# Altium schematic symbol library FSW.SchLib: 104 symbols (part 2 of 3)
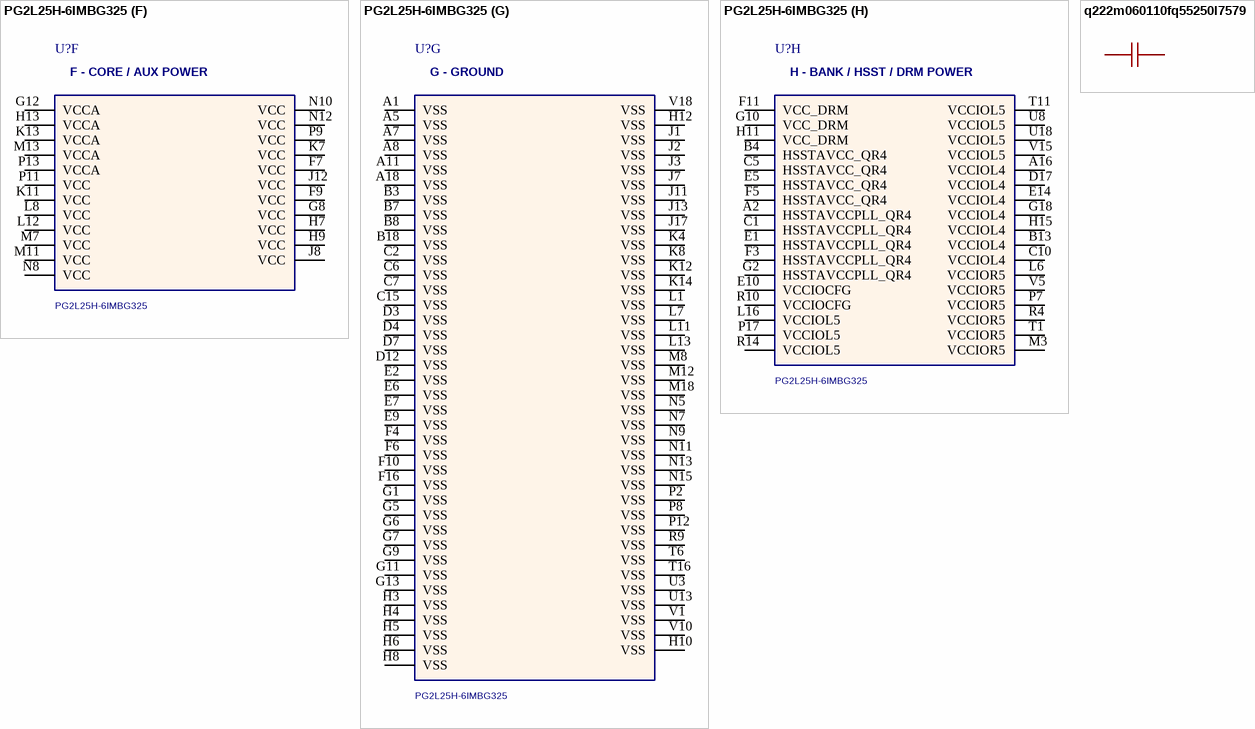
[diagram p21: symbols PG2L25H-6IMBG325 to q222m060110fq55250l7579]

## PG2L25H-6IMBG325
designator U?  (value not drawn)
PANGO Logos2 FPGA; 8 parts; 324 balls; PK04004 V1.1 verified; Reference: OPHW-V1.0.pdf pp2-4
footprint PANGO_MBG325_15X15_P080 (PK04004 V1.1: 324 balls, 15x15mm, 0.8mm pitch; top-view A1 upper-left; nominal 3D 1.30mm, max height 1.45mm)
part A pins: E8 CFG_CLK (io) "OPHW-V1.0.pdf pages 2-4; ball E8", E11 VCCB (power) "OPHW-V1.0.pdf pages 2-4; ball E11", E12 SCBV (in) "OPHW-V1.0.pdf pages 2-4; ball E12", F8 TCK (in) "OPHW-V1.0.pdf pages 2-4; ball F8", F12 CFG_DONE (io) "Bidirectional open-drain. External pull-up required. UG040005 V1.3.", F13 MODE_2 (in) "OPHW-V1.0.pdf pages 2-4; ball F13", J9 VSSADC (power) "OPHW-V1.0.pdf pages 2-4; ball J9", J10 VCCADC (power) "OPHW-V1.0.pdf pages 2-4; ball J10", K9 VREFADC_N (in) "OPHW-V1.0.pdf pages 2-4; ball K9", K10 VAADC_P (in) "OPHW-V1.0.pdf pages 2-4; ball K10", L9 VAADC_N (in) "OPHW-V1.0.pdf pages 2-4; ball L9", L10 VREFADC_P (in) "OPHW-V1.0.pdf pages 2-4; ball L10", M9 TSDN "OPHW-V1.0.pdf pages 2-4; ball M9", M10 TSDP "OPHW-V1.0.pdf pages 2-4; ball M10", P10 RSTN (in) "OPHW-V1.0.pdf pages 2-4; ball P10", R8 TMS (in) "OPHW-V1.0.pdf pages 2-4; ball R8", R11 MODE_1 (in) "OPHW-V1.0.pdf pages 2-4; ball R11", R12 MODE_0 (in) "OPHW-V1.0.pdf pages 2-4; ball R12", T8 TDO (out) "OPHW-V1.0.pdf pages 2-4; ball T8", T9 TDI (in) "OPHW-V1.0.pdf pages 2-4; ball T9", T10 INIT_FLAG_N (io) "Bidirectional open-drain. External pull-up required. UG040005 V1.3."
part B pins: J14 DIFFIO_L5_G0_04P_D6 (io) "OPHW-V1.0.pdf pages 2-4; ball J14", J15 DIFFIO_L5_G0_01P_D2 (io) "OPHW-V1.0.pdf pages 2-4; ball J15", J16 DIFFIO_L5_G0_01N_D3 (io) "OPHW-V1.0.pdf pages 2-4; ball J16", J18 DIFFIO_L5_G0_02P_DQS_IO_STATUS_C (io) "OPHW-V1.0.pdf pages 2-4; ball J18", K15 DIFFIO_L5_G0_04N_D7 (io) "OPHW-V1.0.pdf pages 2-4; ball K15", K16 DIFFIO_L5_G0_00P_MOSI_D0 (io) "OPHW-V1.0.pdf pages 2-4; ball K16", K17 DIFFIO_L5_G0_03P_D4 (io) "OPHW-V1.0.pdf pages 2-4; ball K17", K18 DIFFIO_L5_G0_02N_DQS_ECCLKIN (io) "OPHW-V1.0.pdf pages 2-4; ball K18", L14 SIO_L5_00 (io) "OPHW-V1.0.pdf pages 2-4; ball L14", L15 DIFFIO_L5_G0_05P_FCS_N (io) "OPHW-V1.0.pdf pages 2-4; ball L15", L17 DIFFIO_L5_G0_00N_MISO_D1_DI (io) "OPHW-V1.0.pdf pages 2-4; ball L17", L18 DIFFIO_L5_G0_03N_D5 (io) "OPHW-V1.0.pdf pages 2-4; ball L18", M14 DIFFIO_L5_G1_07P_D11 (io) "OPHW-V1.0.pdf pages 2-4; ball M14", M15 DIFFIO_L5_G0_05N_VREF_D8 (io) "OPHW-V1.0.pdf pages 2-4; ball M15", M16 DIFFIO_L5_G1_06P_D9 (io) "OPHW-V1.0.pdf pages 2-4; ball M16", M17 DIFFIO_L5_G1_06N_D10 (io) "OPHW-V1.0.pdf pages 2-4; ball M17", N14 DIFFIO_L5_G1_07N_D12 (io) "OPHW-V1.0.pdf pages 2-4; ball N14", N16 DIFFIO_L5_G1_08P_DQS (io) "OPHW-V1.0.pdf pages 2-4; ball N16", N17 DIFFIO_L5_G1_08N_DQS_D13 (io) "OPHW-V1.0.pdf pages 2-4; ball N17", N18 DIFFIO_L5_G1_09P_D14 (io) "OPHW-V1.0.pdf pages 2-4; ball N18", P14 DIFFIO_L5_G1_11P_GMCLK (io) "OPHW-V1.0.pdf pages 2-4; ball P14", P15 DIFFIO_L5_G1_10P_GSCLK (io) "OPHW-V1.0.pdf pages 2-4; ball P15", P16 DIFFIO_L5_G1_10N_GSCLK (io) "OPHW-V1.0.pdf pages 2-4; ball P16", P18 DIFFIO_L5_G1_09N_D15 (io) "OPHW-V1.0.pdf pages 2-4; ball P18", R13 DIFFIO_L5_G3_18P_D26_A10 (io) "OPHW-V1.0.pdf pages 2-4; ball R13", R15 DIFFIO_L5_G1_11N_GMCLK (io) "OPHW-V1.0.pdf pages 2-4; ball R15", R16 DIFFIO_L5_G2_13P_GSCLK (io) "OPHW-V1.0.pdf pages 2-4; ball R16", R17 DIFFIO_L5_G2_13N_GSCLK (io) "OPHW-V1.0.pdf pages 2-4; ball R17", R18 DIFFIO_L5_G2_14P_DQS_RWSEL (io) "OPHW-V1.0.pdf pages 2-4; ball R18", T12 DIFFIO_L5_G3_21P_D21_A5 (io) "OPHW-V1.0.pdf pages 2-4; ball T12", T13 DIFFIO_L5_G3_18N_VREF_D25_A9 (io) "OPHW-V1.0.pdf pages 2-4; ball T13", T14 DIFFIO_L5_G2_12P_GMCLK (io) "OPHW-V1.0.pdf pages 2-4; ball T14", T15 DIFFIO_L5_G2_12N_GMCLK (io) "OPHW-V1.0.pdf pages 2-4; ball T15", T17 DIFFIO_L5_G2_15P_CS_N (io) "OPHW-V1.0.pdf pages 2-4; ball T17", T18 DIFFIO_L5_G2_14N_DQS_CSO_DOUT (io) "OPHW-V1.0.pdf pages 2-4; ball T18", U9 DIFFIO_L5_G3_23P_D17_A1 (io) "OPHW-V1.0.pdf pages 2-4; ball U9", U10 SIO_L5_01 (io) "OPHW-V1.0.pdf pages 2-4; ball U10", U11 DIFFIO_L5_G3_22P_D19_A3 (io) "OPHW-V1.0.pdf pages 2-4; ball U11", U12 DIFFIO_L5_G3_21N_D20_A4 (io) "OPHW-V1.0.pdf pages 2-4; ball U12", U14 DIFFIO_L5_G3_19P_D24_A8 (io) "OPHW-V1.0.pdf pages 2-4; ball U14", U15 DIFFIO_L5_G2_16P_D30_A14 (io) "OPHW-V1.0.pdf pages 2-4; ball U15", U16 DIFFIO_L5_G2_16N_D29_A13 (io) "OPHW-V1.0.pdf pages 2-4; ball U16", U17 DIFFIO_L5_G2_15N_D31_A15 (io) "OPHW-V1.0.pdf pages 2-4; ball U17", V9 DIFFIO_L5_G3_23N_D16_A0 (io) "OPHW-V1.0.pdf pages 2-4; ball V9", V11 DIFFIO_L5_G3_22N_D18_A2 (io) "OPHW-V1.0.pdf pages 2-4; ball V11", V12 DIFFIO_L5_G3_20P_DQS (io) "OPHW-V1.0.pdf pages 2-4; ball V12", V13 DIFFIO_L5_G3_20N_DQS_D22_A6 (io) "OPHW-V1.0.pdf pages 2-4; ball V13", V14 DIFFIO_L5_G3_19N_D23_A7 (io) "OPHW-V1.0.pdf pages 2-4; ball V14", V16 DIFFIO_L5_G2_17P_D28_A12 (io) "OPHW-V1.0.pdf pages 2-4; ball V16", V17 DIFFIO_L5_G2_17N_D27_A11 (io) "OPHW-V1.0.pdf pages 2-4; ball V17"
part C pins: A9 DIFFIO_L4_G0_02N_DQS_VAA3N (io) "OPHW-V1.0.pdf pages 2-4; ball A9", A10 DIFFIO_L4_G0_04N_VAA5N (io) "OPHW-V1.0.pdf pages 2-4; ball A10", A12 DIFFIO_L4_G1_06N_VAA7N (io) "OPHW-V1.0.pdf pages 2-4; ball A12", A13 DIFFIO_L4_G1_07P_VAA8P (io) "OPHW-V1.0.pdf pages 2-4; ball A13", A14 DIFFIO_L4_G1_07N_VAA8N (io) "OPHW-V1.0.pdf pages 2-4; ball A14", A15 DIFFIO_L4_G1_09N_VAA10N (io) "OPHW-V1.0.pdf pages 2-4; ball A15", A17 DIFFIO_L4_G2_14N_DQS_BADRVO_N (io) "OPHW-V1.0.pdf pages 2-4; ball A17", B9 DIFFIO_L4_G0_02P_DQS_VAA3P (io) "OPHW-V1.0.pdf pages 2-4; ball B9", B10 DIFFIO_L4_G0_04P_VAA5P (io) "OPHW-V1.0.pdf pages 2-4; ball B10", B11 DIFFIO_L4_G0_03N (io) "OPHW-V1.0.pdf pages 2-4; ball B11", B12 DIFFIO_L4_G1_06P_VAA7P (io) "OPHW-V1.0.pdf pages 2-4; ball B12", B14 DIFFIO_L4_G1_09P_VAA10P (io) "OPHW-V1.0.pdf pages 2-4; ball B14", B15 DIFFIO_L4_G1_08N_DQS_VAA9N (io) "OPHW-V1.0.pdf pages 2-4; ball B15", B16 DIFFIO_L4_G2_14P_DQS (io) "OPHW-V1.0.pdf pages 2-4; ball B16", B17 DIFFIO_L4_G2_15N_A27 (io) "OPHW-V1.0.pdf pages 2-4; ball B17", C8 DIFFIO_L4_G0_00N_VAA1N (io) "OPHW-V1.0.pdf pages 2-4; ball C8", C9 DIFFIO_L4_G0_01N_VAA2N (io) "OPHW-V1.0.pdf pages 2-4; ball C9", C11 DIFFIO_L4_G0_03P (io) "OPHW-V1.0.pdf pages 2-4; ball C11", C12 DIFFIO_L4_G0_05N_VREF (io) "OPHW-V1.0.pdf pages 2-4; ball C12", C13 DIFFIO_L4_G1_10N_GSCLK (io) "OPHW-V1.0.pdf pages 2-4; ball C13", C14 DIFFIO_L4_G1_08P_DQS_VAA9P (io) "OPHW-V1.0.pdf pages 2-4; ball C14", C16 DIFFIO_L4_G2_15P_A28 (io) "OPHW-V1.0.pdf pages 2-4; ball C16", C17 DIFFIO_L4_G2_17P_A24 (io) "OPHW-V1.0.pdf pages 2-4; ball C17", C18 DIFFIO_L4_G2_17N_A23 (io) "OPHW-V1.0.pdf pages 2-4; ball C18", D8 DIFFIO_L4_G0_00P_VAA1P (io) "OPHW-V1.0.pdf pages 2-4; ball D8", D9 DIFFIO_L4_G0_01P_VAA2P (io) "OPHW-V1.0.pdf pages 2-4; ball D9", D10 SIO_L4_00 (io) "OPHW-V1.0.pdf pages 2-4; ball D10", D11 DIFFIO_L4_G0_05P (io) "OPHW-V1.0.pdf pages 2-4; ball D11", D13 DIFFIO_L4_G1_10P_GSCLK (io) "OPHW-V1.0.pdf pages 2-4; ball D13", D14 DIFFIO_L4_G1_11N_GMCLK (io) "OPHW-V1.0.pdf pages 2-4; ball D14", D15 DIFFIO_L4_G2_12N_GMCLK (io) "OPHW-V1.0.pdf pages 2-4; ball D15", D16 DIFFIO_L4_G2_13N_GSCLK (io) "OPHW-V1.0.pdf pages 2-4; ball D16", D18 DIFFIO_L4_G2_16N_A25 (io) "OPHW-V1.0.pdf pages 2-4; ball D18", E13 DIFFIO_L4_G1_11P_GMCLK (io) "OPHW-V1.0.pdf pages 2-4; ball E13", E15 DIFFIO_L4_G2_12P_GMCLK (io) "OPHW-V1.0.pdf pages 2-4; ball E15", E16 DIFFIO_L4_G2_13P_GSCLK (io) "OPHW-V1.0.pdf pages 2-4; ball E16", E17 DIFFIO_L4_G2_16P_A26 (io) "OPHW-V1.0.pdf pages 2-4; ball E17", E18 DIFFIO_L4_G3_23N_VS0 (io) "OPHW-V1.0.pdf pages 2-4; ball E18", F14 DIFFIO_L4_G3_21N_A16 (io) "OPHW-V1.0.pdf pages 2-4; ball F14", F15 DIFFIO_L4_G3_20N_DQS_A18 (io) "OPHW-V1.0.pdf pages 2-4; ball F15", F17 DIFFIO_L4_G3_23P_VS1 (io) "OPHW-V1.0.pdf pages 2-4; ball F17", F18 DIFFIO_L4_G3_18N_VREF_A21 (io) "OPHW-V1.0.pdf pages 2-4; ball F18", G14 DIFFIO_L4_G3_21P_A17 (io) "OPHW-V1.0.pdf pages 2-4; ball G14", G15 DIFFIO_L4_G3_20P_DQS (io) "OPHW-V1.0.pdf pages 2-4; ball G15", G16 DIFFIO_L4_G3_19N_A19 (io) "OPHW-V1.0.pdf pages 2-4; ball G16", G17 DIFFIO_L4_G3_18P_A22 (io) "OPHW-V1.0.pdf pages 2-4; ball G17", H14 SIO_L4_01 (io) "OPHW-V1.0.pdf pages 2-4; ball H14", H16 DIFFIO_L4_G3_19P_A20 (io) "OPHW-V1.0.pdf pages 2-4; ball H16", H17 DIFFIO_L4_G3_22P_BFOE_N (io) "OPHW-V1.0.pdf pages 2-4; ball H17", H18 DIFFIO_L4_G3_22N_BFWE_FCS2_N (io) "OPHW-V1.0.pdf pages 2-4; ball H18"
part D pins: J4 DIFFIO_R5_G0_01N (io) "OPHW-V1.0.pdf pages 2-4; ball J4", J5 DIFFIO_R5_G0_01P (io) "OPHW-V1.0.pdf pages 2-4; ball J5", J6 SIO_R5_00 (io) "OPHW-V1.0.pdf pages 2-4; ball J6", K1 DIFFIO_R5_G0_02N_DQS (io) "OPHW-V1.0.pdf pages 2-4; ball K1", K2 DIFFIO_R5_G0_02P_DQS (io) "OPHW-V1.0.pdf pages 2-4; ball K2", K3 DIFFIO_R5_G0_03P (io) "OPHW-V1.0.pdf pages 2-4; ball K3", K5 DIFFIO_R5_G0_00N (io) "OPHW-V1.0.pdf pages 2-4; ball K5", K6 DIFFIO_R5_G0_00P (io) "OPHW-V1.0.pdf pages 2-4; ball K6", L2 DIFFIO_R5_G0_03N (io) "OPHW-V1.0.pdf pages 2-4; ball L2", L3 DIFFIO_R5_G0_04N (io) "OPHW-V1.0.pdf pages 2-4; ball L3", L4 DIFFIO_R5_G0_04P (io) "OPHW-V1.0.pdf pages 2-4; ball L4", L5 DIFFIO_R5_G0_05P (io) "OPHW-V1.0.pdf pages 2-4; ball L5", M1 DIFFIO_R5_G1_06N (io) "OPHW-V1.0.pdf pages 2-4; ball M1", M2 DIFFIO_R5_G1_06P (io) "OPHW-V1.0.pdf pages 2-4; ball M2", M4 DIFFIO_R5_G1_09P (io) "OPHW-V1.0.pdf pages 2-4; ball M4", M5 DIFFIO_R5_G0_05N_VREF (io) "OPHW-V1.0.pdf pages 2-4; ball M5", M6 DIFFIO_R5_G1_07P (io) "OPHW-V1.0.pdf pages 2-4; ball M6", N1 DIFFIO_R5_G1_08P_DQS (io) "OPHW-V1.0.pdf pages 2-4; ball N1", N2 DIFFIO_R5_G1_10N_GSCLK (io) "OPHW-V1.0.pdf pages 2-4; ball N2", N3 DIFFIO_R5_G1_10P_GSCLK (io) "OPHW-V1.0.pdf pages 2-4; ball N3", N4 DIFFIO_R5_G1_09N (io) "OPHW-V1.0.pdf pages 2-4; ball N4", N6 DIFFIO_R5_G1_07N (io) "OPHW-V1.0.pdf pages 2-4; ball N6", P1 DIFFIO_R5_G1_08N_DQS (io) "OPHW-V1.0.pdf pages 2-4; ball P1", P3 DIFFIO_R5_G1_11N_GMCLK (io) "OPHW-V1.0.pdf pages 2-4; ball P3", P4 DIFFIO_R5_G1_11P_GMCLK (io) "OPHW-V1.0.pdf pages 2-4; ball P4", P5 DIFFIO_R5_G3_18N_VREF (io) "OPHW-V1.0.pdf pages 2-4; ball P5", P6 DIFFIO_R5_G3_18P (io) "OPHW-V1.0.pdf pages 2-4; ball P6", R1 DIFFIO_R5_G2_12N_GMCLK (io) "OPHW-V1.0.pdf pages 2-4; ball R1", R2 DIFFIO_R5_G2_12P_GMCLK (io) "OPHW-V1.0.pdf pages 2-4; ball R2", R3 DIFFIO_R5_G2_13P_GSCLK (io) "OPHW-V1.0.pdf pages 2-4; ball R3", R5 DIFFIO_R5_G3_20P_DQS (io) "OPHW-V1.0.pdf pages 2-4; ball R5", R6 SIO_R5_01 (io) "OPHW-V1.0.pdf pages 2-4; ball R6", R7 DIFFIO_R5_G3_21P (io) "OPHW-V1.0.pdf pages 2-4; ball R7", T2 DIFFIO_R5_G2_13N_GSCLK (io) "OPHW-V1.0.pdf pages 2-4; ball T2", T3 DIFFIO_R5_G2_16N (io) "OPHW-V1.0.pdf pages 2-4; ball T3", T4 DIFFIO_R5_G2_16P (io) "OPHW-V1.0.pdf pages 2-4; ball T4", T5 DIFFIO_R5_G3_20N_DQS (io) "OPHW-V1.0.pdf pages 2-4; ball T5", T7 DIFFIO_R5_G3_21N (io) "OPHW-V1.0.pdf pages 2-4; ball T7", U1 DIFFIO_R5_G2_14N_DQS (io) "OPHW-V1.0.pdf pages 2-4; ball U1", U2 DIFFIO_R5_G2_14P_DQS (io) "OPHW-V1.0.pdf pages 2-4; ball U2", U4 DIFFIO_R5_G2_17P (io) "OPHW-V1.0.pdf pages 2-4; ball U4", U5 DIFFIO_R5_G3_19N (io) "OPHW-V1.0.pdf pages 2-4; ball U5", U6 DIFFIO_R5_G3_19P (io) "OPHW-V1.0.pdf pages 2-4; ball U6", U7 DIFFIO_R5_G3_22P (io) "OPHW-V1.0.pdf pages 2-4; ball U7", V2 DIFFIO_R5_G2_15N (io) "OPHW-V1.0.pdf pages 2-4; ball V2", V3 DIFFIO_R5_G2_15P (io) "OPHW-V1.0.pdf pages 2-4; ball V3", V4 DIFFIO_R5_G2_17N (io) "OPHW-V1.0.pdf pages 2-4; ball V4", V6 DIFFIO_R5_G3_22N (io) "OPHW-V1.0.pdf pages 2-4; ball V6", V7 DIFFIO_R5_G3_23N (io) "OPHW-V1.0.pdf pages 2-4; ball V7", V8 DIFFIO_R5_G3_23P (io) "OPHW-V1.0.pdf pages 2-4; ball V8"
part E pins: A3 HSSTRX2N_QR4 (in) "OPHW-V1.0.pdf pages 2-4; ball A3", A4 HSSTRX2P_QR4 (in) "OPHW-V1.0.pdf pages 2-4; ball A4", A6 HSSTRREF_QR4 (in) "OPHW-V1.0.pdf pages 2-4; ball A6", B1 HSSTTX0N_QR4 (out) "OPHW-V1.0.pdf pages 2-4; ball B1", B2 HSSTTX0P_QR4 (out) "OPHW-V1.0.pdf pages 2-4; ball B2", B5 HSSTREFCLK0N_QR4 (in) "OPHW-V1.0.pdf pages 2-4; ball B5", B6 HSSTREFCLK0P_QR4 (in) "OPHW-V1.0.pdf pages 2-4; ball B6", C3 HSSTRX1N_QR4 (in) "OPHW-V1.0.pdf pages 2-4; ball C3", C4 HSSTRX1P_QR4 (in) "OPHW-V1.0.pdf pages 2-4; ball C4", D1 HSSTTX1N_QR4 (out) "OPHW-V1.0.pdf pages 2-4; ball D1", D2 HSSTTX1P_QR4 (out) "OPHW-V1.0.pdf pages 2-4; ball D2", D5 HSSTREFCLK1N_QR4 (in) "OPHW-V1.0.pdf pages 2-4; ball D5", D6 HSSTREFCLK1P_QR4 (in) "OPHW-V1.0.pdf pages 2-4; ball D6", E3 HSSTRX3N_QR4 (in) "OPHW-V1.0.pdf pages 2-4; ball E3", E4 HSSTRX3P_QR4 (in) "OPHW-V1.0.pdf pages 2-4; ball E4", F1 HSSTTX2N_QR4 (out) "OPHW-V1.0.pdf pages 2-4; ball F1", F2 HSSTTX2P_QR4 (out) "OPHW-V1.0.pdf pages 2-4; ball F2", G3 HSSTRX0N_QR4 (in) "OPHW-V1.0.pdf pages 2-4; ball G3", G4 HSSTRX0P_QR4 (in) "OPHW-V1.0.pdf pages 2-4; ball G4", H1 HSSTTX3N_QR4 (out) "OPHW-V1.0.pdf pages 2-4; ball H1", H2 HSSTTX3P_QR4 (out) "OPHW-V1.0.pdf pages 2-4; ball H2"
part F pins: F7 VCC (power) "OPHW-V1.0.pdf pages 2-4; ball F7", F9 VCC (power) "OPHW-V1.0.pdf pages 2-4; ball F9", G8 VCC (power) "OPHW-V1.0.pdf pages 2-4; ball G8", G12 VCCA (power) "OPHW-V1.0.pdf pages 2-4; ball G12", H7 VCC (power) "OPHW-V1.0.pdf pages 2-4; ball H7", H9 VCC (power) "OPHW-V1.0.pdf pages 2-4; ball H9", H13 VCCA (power) "OPHW-V1.0.pdf pages 2-4; ball H13", J8 VCC (power) "OPHW-V1.0.pdf pages 2-4; ball J8", J12 VCC (power) "OPHW-V1.0.pdf pages 2-4; ball J12", K7 VCC (power) "OPHW-V1.0.pdf pages 2-4; ball K7", K11 VCC (power) "OPHW-V1.0.pdf pages 2-4; ball K11", K13 VCCA (power) "OPHW-V1.0.pdf pages 2-4; ball K13", L8 VCC (power) "OPHW-V1.0.pdf pages 2-4; ball L8", L12 VCC (power) "OPHW-V1.0.pdf pages 2-4; ball L12", M7 VCC (power) "OPHW-V1.0.pdf pages 2-4; ball M7", M11 VCC (power) "OPHW-V1.0.pdf pages 2-4; ball M11", M13 VCCA (power) "OPHW-V1.0.pdf pages 2-4; ball M13", N8 VCC (power) "OPHW-V1.0.pdf pages 2-4; ball N8", N10 VCC (power) "OPHW-V1.0.pdf pages 2-4; ball N10", N12 VCC (power) "OPHW-V1.0.pdf pages 2-4; ball N12", P9 VCC (power) "OPHW-V1.0.pdf pages 2-4; ball P9", P11 VCC (power) "OPHW-V1.0.pdf pages 2-4; ball P11", P13 VCCA (power) "OPHW-V1.0.pdf pages 2-4; ball P13"
part G pins: A1 VSS (power) "OPHW-V1.0.pdf pages 2-4; ball A1", A5 VSS (power) "OPHW-V1.0.pdf pages 2-4; ball A5", A7 VSS (power) "OPHW-V1.0.pdf pages 2-4; ball A7", A8 VSS (power) "OPHW-V1.0.pdf pages 2-4; ball A8", A11 VSS (power) "OPHW-V1.0.pdf pages 2-4; ball A11", A18 VSS (power) "OPHW-V1.0.pdf pages 2-4; ball A18", B3 VSS (power) "OPHW-V1.0.pdf pages 2-4; ball B3", B7 VSS (power) "OPHW-V1.0.pdf pages 2-4; ball B7", B8 VSS (power) "OPHW-V1.0.pdf pages 2-4; ball B8", B18 VSS (power) "OPHW-V1.0.pdf pages 2-4; ball B18", C2 VSS (power) "OPHW-V1.0.pdf pages 2-4; ball C2", C6 VSS (power) "OPHW-V1.0.pdf pages 2-4; ball C6", C7 VSS (power) "OPHW-V1.0.pdf pages 2-4; ball C7", C15 VSS (power) "OPHW-V1.0.pdf pages 2-4; ball C15", D3 VSS (power) "OPHW-V1.0.pdf pages 2-4; ball D3", D4 VSS (power) "OPHW-V1.0.pdf pages 2-4; ball D4", D7 VSS (power) "OPHW-V1.0.pdf pages 2-4; ball D7", D12 VSS (power) "OPHW-V1.0.pdf pages 2-4; ball D12", E2 VSS (power) "OPHW-V1.0.pdf pages 2-4; ball E2", E6 VSS (power) "OPHW-V1.0.pdf pages 2-4; ball E6", E7 VSS (power) "OPHW-V1.0.pdf pages 2-4; ball E7", E9 VSS (power) "OPHW-V1.0.pdf pages 2-4; ball E9", F4 VSS (power) "OPHW-V1.0.pdf pages 2-4; ball F4", F6 VSS (power) "OPHW-V1.0.pdf pages 2-4; ball F6", F10 VSS (power) "OPHW-V1.0.pdf pages 2-4; ball F10", F16 VSS (power) "OPHW-V1.0.pdf pages 2-4; ball F16", G1 VSS (power) "OPHW-V1.0.pdf pages 2-4; ball G1", G5 VSS (power) "OPHW-V1.0.pdf pages 2-4; ball G5", G6 VSS (power) "OPHW-V1.0.pdf pages 2-4; ball G6", G7 VSS (power) "OPHW-V1.0.pdf pages 2-4; ball G7", G9 VSS (power) "OPHW-V1.0.pdf pages 2-4; ball G9", G11 VSS (power) "OPHW-V1.0.pdf pages 2-4; ball G11", G13 VSS (power) "OPHW-V1.0.pdf pages 2-4; ball G13", H3 VSS (power) "OPHW-V1.0.pdf pages 2-4; ball H3", H4 VSS (power) "OPHW-V1.0.pdf pages 2-4; ball H4", H5 VSS (power) "OPHW-V1.0.pdf pages 2-4; ball H5", H6 VSS (power) "OPHW-V1.0.pdf pages 2-4; ball H6", H8 VSS (power) "OPHW-V1.0.pdf pages 2-4; ball H8", H10 VSS (power) "OPHW-V1.0.pdf pages 2-4; ball H10", H12 VSS (power) "OPHW-V1.0.pdf pages 2-4; ball H12", J1 VSS (power) "OPHW-V1.0.pdf pages 2-4; ball J1", J2 VSS (power) "OPHW-V1.0.pdf pages 2-4; ball J2", J3 VSS (power) "OPHW-V1.0.pdf pages 2-4; ball J3", J7 VSS (power) "OPHW-V1.0.pdf pages 2-4; ball J7", J11 VSS (power) "OPHW-V1.0.pdf pages 2-4; ball J11", J13 VSS (power) "OPHW-V1.0.pdf pages 2-4; ball J13", J17 VSS (power) "OPHW-V1.0.pdf pages 2-4; ball J17", K4 VSS (power) "OPHW-V1.0.pdf pages 2-4; ball K4", K8 VSS (power) "OPHW-V1.0.pdf pages 2-4; ball K8", K12 VSS (power) "OPHW-V1.0.pdf pages 2-4; ball K12", K14 VSS (power) "OPHW-V1.0.pdf pages 2-4; ball K14", L1 VSS (power) "OPHW-V1.0.pdf pages 2-4; ball L1", L7 VSS (power) "OPHW-V1.0.pdf pages 2-4; ball L7", L11 VSS (power) "OPHW-V1.0.pdf pages 2-4; ball L11", L13 VSS (power) "OPHW-V1.0.pdf pages 2-4; ball L13", M8 VSS (power) "OPHW-V1.0.pdf pages 2-4; ball M8", M12 VSS (power) "OPHW-V1.0.pdf pages 2-4; ball M12", M18 VSS (power) "OPHW-V1.0.pdf pages 2-4; ball M18", N5 VSS (power) "OPHW-V1.0.pdf pages 2-4; ball N5", N7 VSS (power) "OPHW-V1.0.pdf pages 2-4; ball N7", N9 VSS (power) "OPHW-V1.0.pdf pages 2-4; ball N9", N11 VSS (power) "OPHW-V1.0.pdf pages 2-4; ball N11", N13 VSS (power) "OPHW-V1.0.pdf pages 2-4; ball N13", N15 VSS (power) "OPHW-V1.0.pdf pages 2-4; ball N15", P2 VSS (power) "OPHW-V1.0.pdf pages 2-4; ball P2", P8 VSS (power) "OPHW-V1.0.pdf pages 2-4; ball P8", P12 VSS (power) "OPHW-V1.0.pdf pages 2-4; ball P12", R9 VSS (power) "OPHW-V1.0.pdf pages 2-4; ball R9", T6 VSS (power) "OPHW-V1.0.pdf pages 2-4; ball T6", T16 VSS (power) "OPHW-V1.0.pdf pages 2-4; ball T16", U3 VSS (power) "OPHW-V1.0.pdf pages 2-4; ball U3", U13 VSS (power) "OPHW-V1.0.pdf pages 2-4; ball U13", V1 VSS (power) "OPHW-V1.0.pdf pages 2-4; ball V1", V10 VSS (power) "OPHW-V1.0.pdf pages 2-4; ball V10", V18 VSS (power) "OPHW-V1.0.pdf pages 2-4; ball V18"
part H pins: A2 HSSTAVCCPLL_QR4 (power) "OPHW-V1.0.pdf pages 2-4; ball A2", A16 VCCIOL4 (power) "OPHW-V1.0.pdf pages 2-4; ball A16", B4 HSSTAVCC_QR4 (power) "OPHW-V1.0.pdf pages 2-4; ball B4", B13 VCCIOL4 (power) "OPHW-V1.0.pdf pages 2-4; ball B13", C1 HSSTAVCCPLL_QR4 (power) "OPHW-V1.0.pdf pages 2-4; ball C1", C5 HSSTAVCC_QR4 (power) "OPHW-V1.0.pdf pages 2-4; ball C5", C10 VCCIOL4 (power) "OPHW-V1.0.pdf pages 2-4; ball C10", D17 VCCIOL4 (power) "OPHW-V1.0.pdf pages 2-4; ball D17", E1 HSSTAVCCPLL_QR4 (power) "OPHW-V1.0.pdf pages 2-4; ball E1", E5 HSSTAVCC_QR4 (power) "OPHW-V1.0.pdf pages 2-4; ball E5", E10 VCCIOCFG (power) "OPHW-V1.0.pdf pages 2-4; ball E10", E14 VCCIOL4 (power) "OPHW-V1.0.pdf pages 2-4; ball E14", F3 HSSTAVCCPLL_QR4 (power) "OPHW-V1.0.pdf pages 2-4; ball F3", F5 HSSTAVCC_QR4 (power) "OPHW-V1.0.pdf pages 2-4; ball F5", F11 VCC_DRM (power) "OPHW-V1.0.pdf pages 2-4; ball F11", G2 HSSTAVCCPLL_QR4 (power) "OPHW-V1.0.pdf pages 2-4; ball G2", G10 VCC_DRM (power) "OPHW-V1.0.pdf pages 2-4; ball G10", G18 VCCIOL4 (power) "OPHW-V1.0.pdf pages 2-4; ball G18", H11 VCC_DRM (power) "OPHW-V1.0.pdf pages 2-4; ball H11", H15 VCCIOL4 (power) "OPHW-V1.0.pdf pages 2-4; ball H15", L6 VCCIOR5 (power) "OPHW-V1.0.pdf pages 2-4; ball L6", L16 VCCIOL5 (power) "OPHW-V1.0.pdf pages 2-4; ball L16", M3 VCCIOR5 (power) "OPHW-V1.0.pdf pages 2-4; ball M3", P7 VCCIOR5 (power) "OPHW-V1.0.pdf pages 2-4; ball P7", P17 VCCIOL5 (power) "OPHW-V1.0.pdf pages 2-4; ball P17", R4 VCCIOR5 (power) "OPHW-V1.0.pdf pages 2-4; ball R4", R10 VCCIOCFG (power) "OPHW-V1.0.pdf pages 2-4; ball R10", R14 VCCIOL5 (power) "OPHW-V1.0.pdf pages 2-4; ball R14", T1 VCCIOR5 (power) "OPHW-V1.0.pdf pages 2-4; ball T1", T11 VCCIOL5 (power) "OPHW-V1.0.pdf pages 2-4; ball T11", U8 VCCIOL5 (power) "OPHW-V1.0.pdf pages 2-4; ball U8", U18 VCCIOL5 (power) "OPHW-V1.0.pdf pages 2-4; ball U18", V5 VCCIOR5 (power) "OPHW-V1.0.pdf pages 2-4; ball V5", V15 VCCIOL5 (power) "OPHW-V1.0.pdf pages 2-4; ball V15"

## q222m060110fq55250l7579
designator C??  (value not drawn)
容值:2.2nF;精度:±20%;工作电压(AC):300V;防护等级:Y2;; Manufacturer: QNR(勤宏科技); AddInBom: yes; ModelId: 6309ea5c534b4b05939c21f9c59ffb79; ModelName: CAP-TH_L8.0-W4.5-P7.50-D0.6; ModelTransform: 354.33,177.165,0,0,0,0,0,0,-196.85; Value: 2.2nF; Tolerance: ±20%; Voltage(AC): 300V; Ratings: Y2
footprint CAP-TH_L8.0-W4.5-P7.50-D0.6
pins: 1, 2

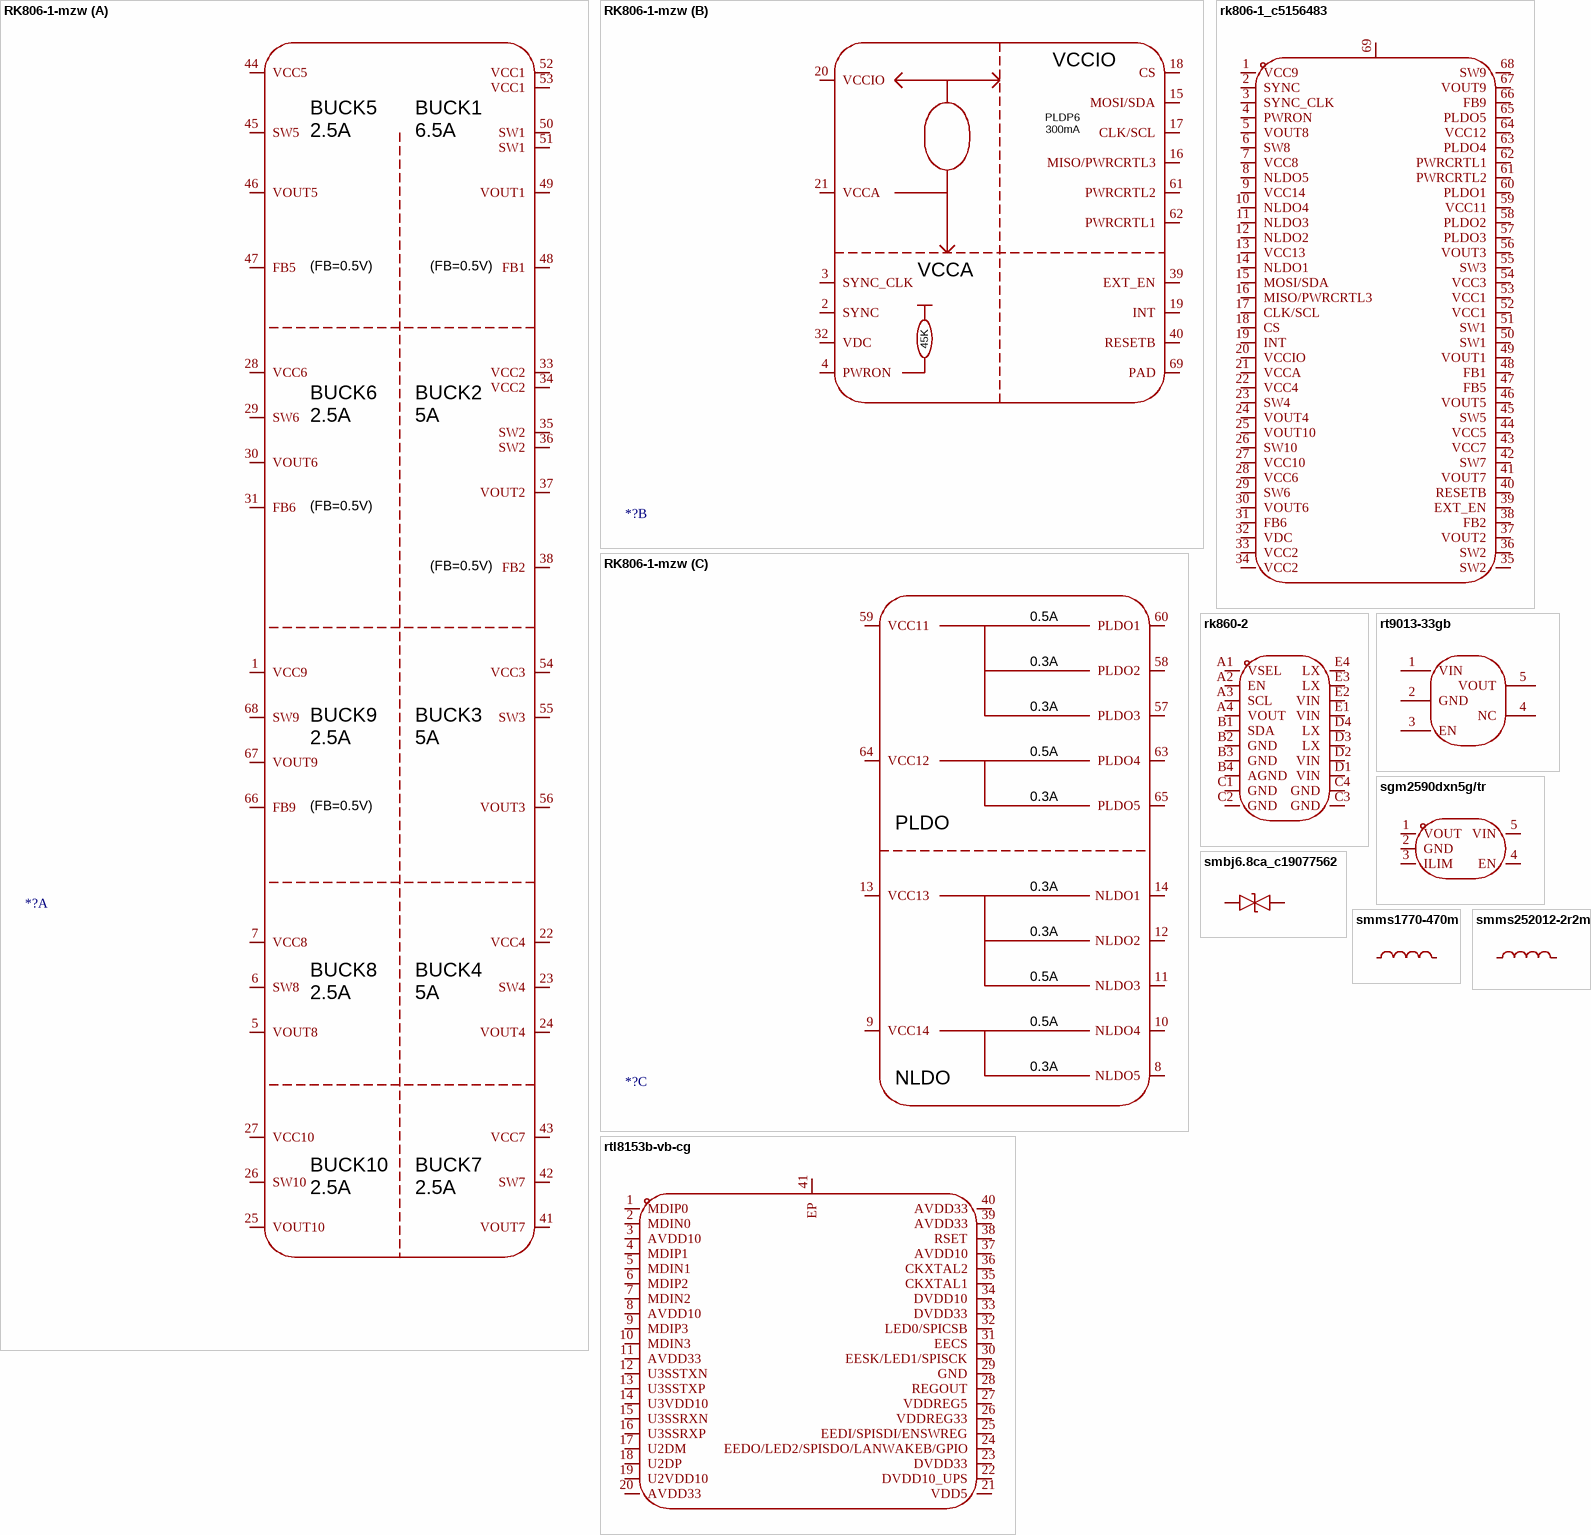
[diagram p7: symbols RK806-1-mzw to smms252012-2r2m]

## RK806-1-mzw
designator *?  (value not drawn)
part A pins: 1 VCC9, 5 VOUT8, 6 SW8, 7 VCC8, 22 VCC4, 23 SW4, 24 VOUT4, 25 VOUT10, 26 SW10, 27 VCC10, 28 VCC6, 29 SW6, 30 VOUT6, 31 FB6, 33 VCC2, 34 VCC2, 35 SW2, 36 SW2, 37 VOUT2, 38 FB2, 41 VOUT7, 42 SW7, 43 VCC7, 44 VCC5, 45 SW5, 46 VOUT5, 47 FB5, 48 FB1, 49 VOUT1, 50 SW1, 51 SW1, 52 VCC1, 53 VCC1, 54 VCC3, 55 SW3, 56 VOUT3, 66 FB9, 67 VOUT9, 68 SW9
part B pins: 2 SYNC, 3 SYNC_CLK, 4 PWRON, 15 MOSI/SDA, 16 MISO/PWRCRTL3, 17 CLK/SCL, 18 CS, 19 INT, 20 VCCIO, 21 VCCA, 32 VDC, 39 EXT_EN, 40 RESETB, 61 PWRCRTL2, 62 PWRCRTL1, 69 PAD
part C pins: 8 NLDO5, 9 VCC14, 10 NLDO4, 11 NLDO3, 12 NLDO2, 13 VCC13, 14 NLDO1, 57 PLDO3, 58 PLDO2, 59 VCC11, 60 PLDO1, 63 PLDO4, 64 VCC12, 65 PLDO5

## rk806-1_c5156483
designator U??  (value not drawn)
RK806是一款复杂的电源管理集成电路（PMIC）。RK806只需极少的外部元件，就能提供完整的电源管理解决方案。RK806提供10个快速负载瞬态同步降压转换器; Manufacturer: Rockchip(瑞芯微); AddInBom: yes; ModelId: e930c577e1fa4bd28a96171513c1b833; ModelName: QFN-68_L7.0-W7.0-H0.8-P0.35-BL-EP5.5; ModelTransform: 275.591,275.591,0,0,0,0,0,0,0; Interface: I2C；SPI; Input Voltage: 2.7V~5.5V; Output Voltage: 0.5V~3.4V; Output Current: 0.5A；0.3A；3A；6.5A；5A
footprint QFN-68_L7.0-W7.0-P0.35-BL-EP5.5
pins: 1 VCC9, 2 SYNC, 3 SYNC_CLK, 4 PWRON, 5 VOUT8, 6 SW8, 7 VCC8, 8 NLDO5, 9 VCC14, 10 NLDO4, 11 NLDO3, 12 NLDO2, 13 VCC13, 14 NLDO1, 15 MOSI/SDA, 16 MISO/PWRCRTL3, 17 CLK/SCL, 18 CS, 19 INT, 20 VCCIO, 21 VCCA, 22 VCC4, 23 SW4, 24 VOUT4, 25 VOUT10, 26 SW10, 27 VCC10, 28 VCC6, 29 SW6, 30 VOUT6, 31 FB6, 32 VDC, 33 VCC2, 34 VCC2, 35 SW2, 36 SW2, 37 VOUT2, 38 FB2, 39 EXT_EN, 40 RESETB, 41 VOUT7, 42 SW7, 43 VCC7, 44 VCC5, 45 SW5, 46 VOUT5, 47 FB5, 48 FB1, 49 VOUT1, 50 SW1, 51 SW1, 52 VCC1, 53 VCC1, 54 VCC3, 55 SW3, 56 VOUT3, 57 PLDO3, 58 PLDO2, 59 VCC11, 60 PLDO1, 61 PWRCRTL2, 62 PWRCRTL1, 63 PLDO4, 64 VCC12, 65 PLDO5, 66 FB9, 67 VOUT9, 68 SW9, 69 PAD

## rk860-2
designator U??  (value not drawn)
功能类型:降压型;工作电压:2.7V~5.5V;输出电压:500mV~1.5V;输出电流:7A;输出类型:-;; Manufacturer: Rockchip(瑞芯微); AddInBom: yes; ModelId: 67b7f17ab7bf4dc098c4da6ba2858108; ModelName: WLCSP-20_L2.0-W1.6-R5-C4-P0.40-TL; ModelTransform: 63.58255,79.33055,0,0,0,0,-0.005,-0.001,0; Function: 降压型; Output Current: 7A; Frequency - Switching: 2.4MHz; Synchronous Rectifier: 是; Number of Outputs: 1; Topology: 降压式; Quiescent Current: 70uA; Switch tube (built-in/external): 内置
footprint WLCSP-20_L2.0-W1.6-R5-C4-P0.40-TL
pins: A1 VSEL, A2 EN, A3 SCL, A4 VOUT, B1 SDA, B2 GND, B3 GND, B4 AGND, C1 GND, C2 GND, C3 GND, C4 GND, D1 VIN, D2 VIN, D3 LX, D4 LX, E1 VIN, E2 VIN, E3 LX, E4 LX

## rt9013-33gb
designator U??  (value not drawn)
输出极性:正极;工作电压:5.5V;输出电压:3.3V;输出电流:500mA;电源纹波抑制比(PSRR):50dB@(10kHz);输出类型:固定;; Manufacturer: RICHTEK(立锜); AddInBom: yes; ModelId: 0a2a1b8f50944f73965918ad6e5fe167; ModelName: SOT-23-5_L2.9-W1.6-H1.1-LS2.8-P0.95; ModelTransform: 118.60433,114.173,0,90,0,0,0.0005,0.0005,0; Output Configuration: 正极; Voltage - Supply: 5.5V; Output Voltage: 3.3V; Output Current: 500mA; Voltage Dropout: 400mV@(500mA); standby current: 25uA; Noise: 30uVrms; Output Type: 固定; Number of Outputs: 1
footprint SOT-23-5_L3.0-W1.7-P0.95-LS2.8-BL
pins: 1 VIN, 2 GND, 3 EN, 4 NC, 5 VOUT

## rtl8153b-vb-cg
designator U??  (value not drawn)
类型:-;端口数量:1;MAC接口:-;; Manufacturer: REALTEK(瑞昱); AddInBom: yes; ModelId: f658c93bb71c4057b80d8d21cfcdd805; ModelName: QFN-40_L5.0-W5.0-H0.9-P0.4-BL-EP; ModelTransform: 196.85,196.85,0,90,0,0,0,0,0; Number of ports: 1; Ethernet Speed Standards: 1000BASE-T；10BASE-T；100BASE-TX; Data Rate: 10Mbit/s；100Mbit/s；1Gbit/s; Voltage - Supply: 3.3V；1V；5V
footprint QFN-40_L5.0-W5.0-P0.40-BL-EP3.7
pins: 1 MDIP0, 2 MDIN0, 3 AVDD10, 4 MDIP1, 5 MDIN1, 6 MDIP2, 7 MDIN2, 8 AVDD10, 9 MDIP3, 10 MDIN3, 11 AVDD33, 12 U3SSTXN, 13 U3SSTXP, 14 U3VDD10, 15 U3SSRXN, 16 U3SSRXP, 17 U2DM, 18 U2DP, 19 U2VDD10, 20 AVDD33, 21 VDD5, 22 DVDD10_UPS, 23 DVDD33, 24 EEDO/LED2/SPISDO/LANWAKEB/GPIO, 25 EEDI/SPISDI/ENSWREG, 26 VDDREG33, 27 VDDREG5, 28 REGOUT, 29 GND, 30 EESK/LED1/SPISCK, 31 EECS, 32 LED0/SPICSB, 33 DVDD33, 34 DVDD10, 35 CKXTAL1, 36 CKXTAL2, 37 AVDD10, 38 RSET, 39 AVDD33, 40 AVDD33, 41 EP

## sgm2590dxn5g/tr
designator U??  (value not drawn)
Manufacturer: SGMICRO(圣邦微); AddInBom: yes; ModelId: 0a2a1b8f50944f73965918ad6e5fe167; ModelName: SOT-23-5_L2.9-W1.6-H1.1-LS2.8-P0.95; ModelTransform: 118.60433,114.173,0,90,0,0,0.0005,0.0005,0
footprint SOT-23-5_L3.0-W1.7-P0.95-LS2.8-BL
pins: 1 VOUT, 2 GND, 3 ILIM, 4 EN, 5 VIN

## smbj6.8ca_c19077562
designator D??  (value not drawn)
极性:双向;反向截止电压(Vrwm):5.8V;钳位电压:10.5V;峰值脉冲电流(Ipp):57.1A;峰值脉冲功率(Ppp):600W@10/1000us;击穿电压(VBR):6.46V;; Manufacturer: R+O(宏嘉诚); AddInBom: yes; ModelId: c0b8639b880e4a4bb7f1ec731307fbc2; ModelName: SMB_L4.3-W3.6-LS5.4-BI; ModelTransform: 212.598,142.5194,0,0,0,0,0,0,0; Polarity: 双向; Reverse Stand-Off Voltage (Vrwm): 5.8V; Clamping Voltage: 10.5V; Peak Pulse Current (Ipp): 57.1A; Voltage - Breakdown: 6.46V; Reverse Leakage Current (Ir): 1mA; Number of Channels: 单路; level of protection: IEC 61000-4-2; Type: TVS
footprint SMB_L4.3-W3.6-LS5.4-BI
pins: 1 K, 2 A

## smms1770-470m
designator U??  (value not drawn)
电感值:47uH;精度:±20%;额定电流:8.7A;饱和电流(Isat):16A;类型:一体成型电感;; Manufacturer: SXN(顺翔诺); AddInBom: yes; ModelId: d1dffc4284db41038928bca88ac39480; ModelName: IND-SMD_L17.5-W17.2-H7.0; ModelTransform: 688.975,675.19948,0,0,0,0,0,0,0; Value: 47uH; Tolerance: ±20%; Rated Current: 8.7A; Saturation Current (Isat): 16A; DC Resistance (DCR): 55mΩ
footprint IND-SMD_L17.5-W17.2
pins: 1, 2

## smms252012-2r2m
designator L??  (value not drawn)
电感值:2.2uH;精度:±20%;额定电流:3A;饱和电流(Isat):3.8A;类型:磁胶屏蔽电感;; Manufacturer: SXN(顺翔诺); AddInBom: yes; ModelId: 94dc9c04db714140b05057b13e968e87; ModelName: IND-SMD_L2.5-W2.0_AFE252010S; ModelTransform: 98.425,78.74,0,0,0,0,0,0,0; Value: 2.2uH; Tolerance: ±20%; Current Rating: 3A; Current - Saturation(Isat): 3.8A; DC Resistance(DCR): 55mΩ; Type: 磁胶屏蔽电感
footprint IND-SMD_L2.5-W2.0_AFE252010S
pins: 1, 2

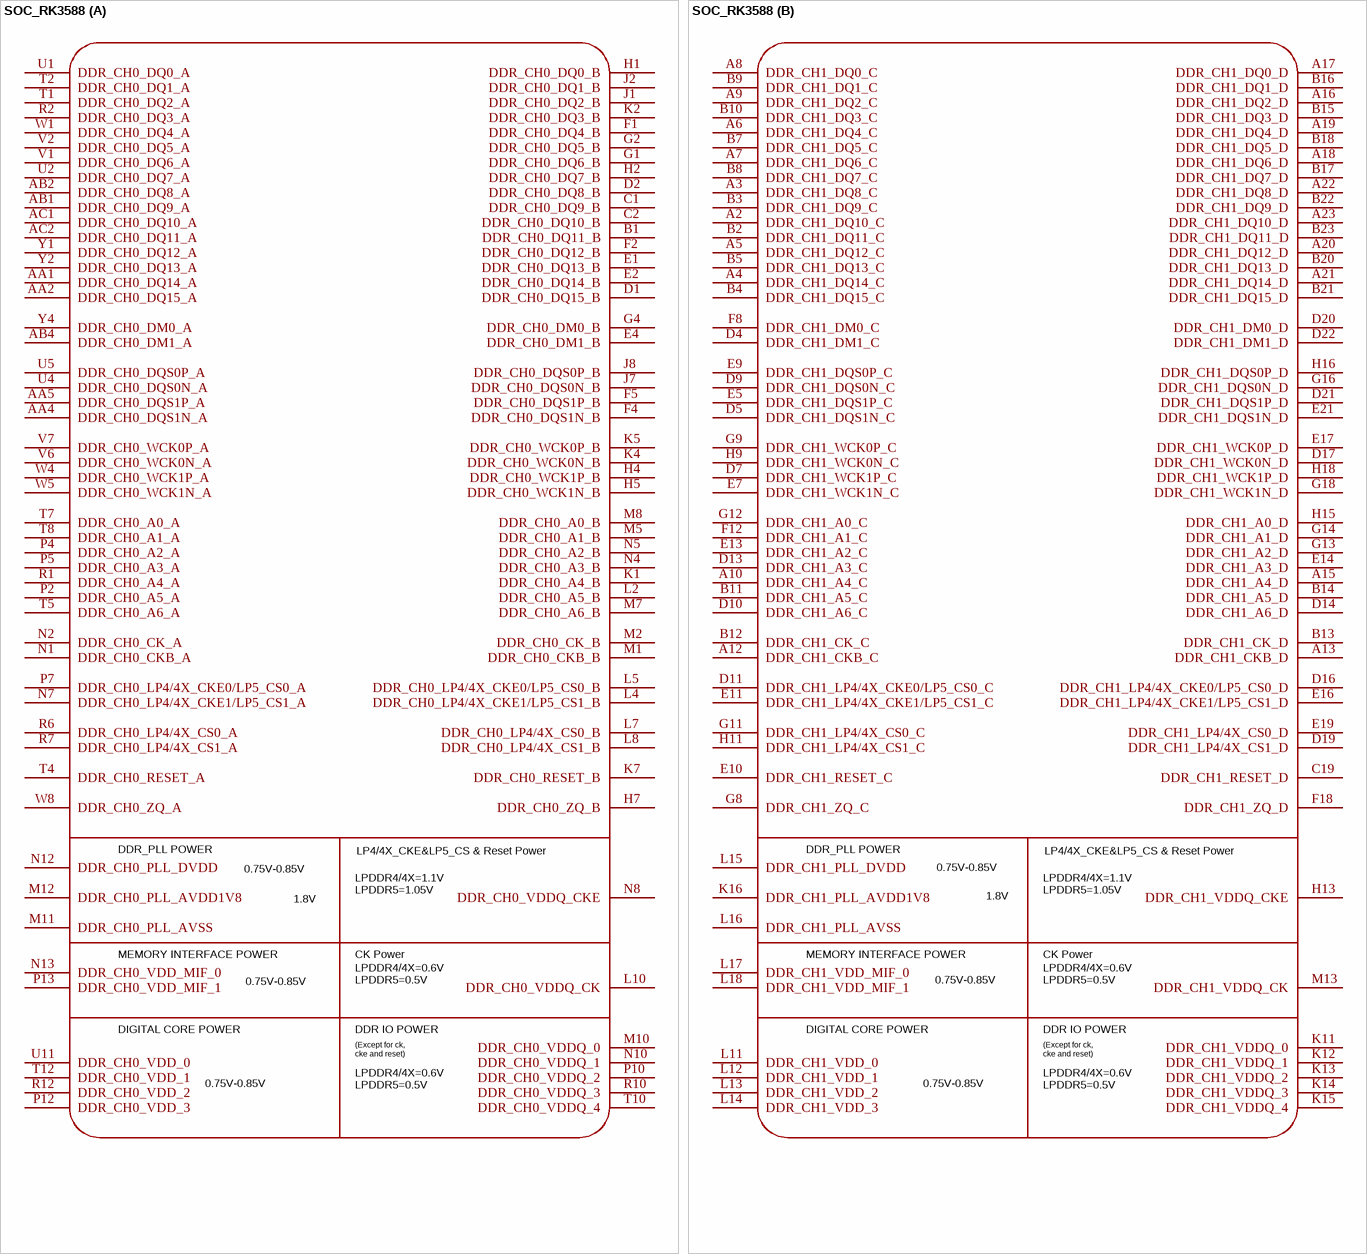
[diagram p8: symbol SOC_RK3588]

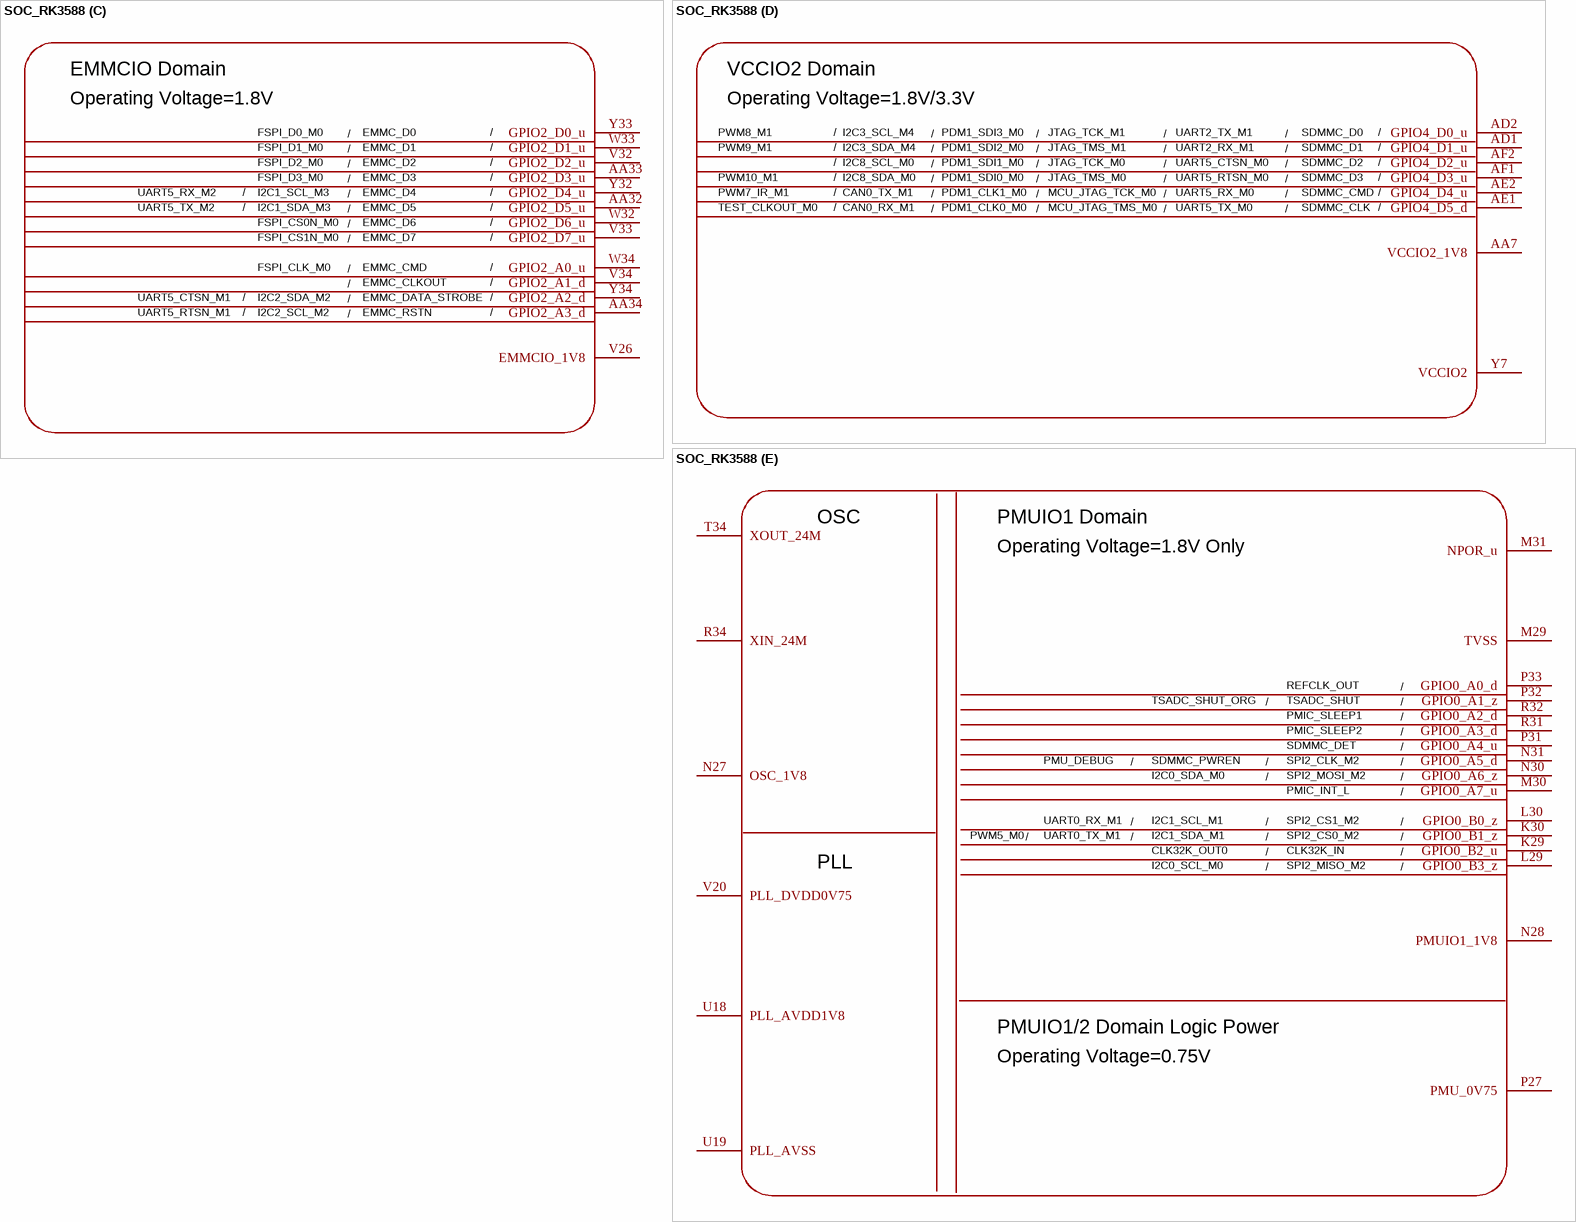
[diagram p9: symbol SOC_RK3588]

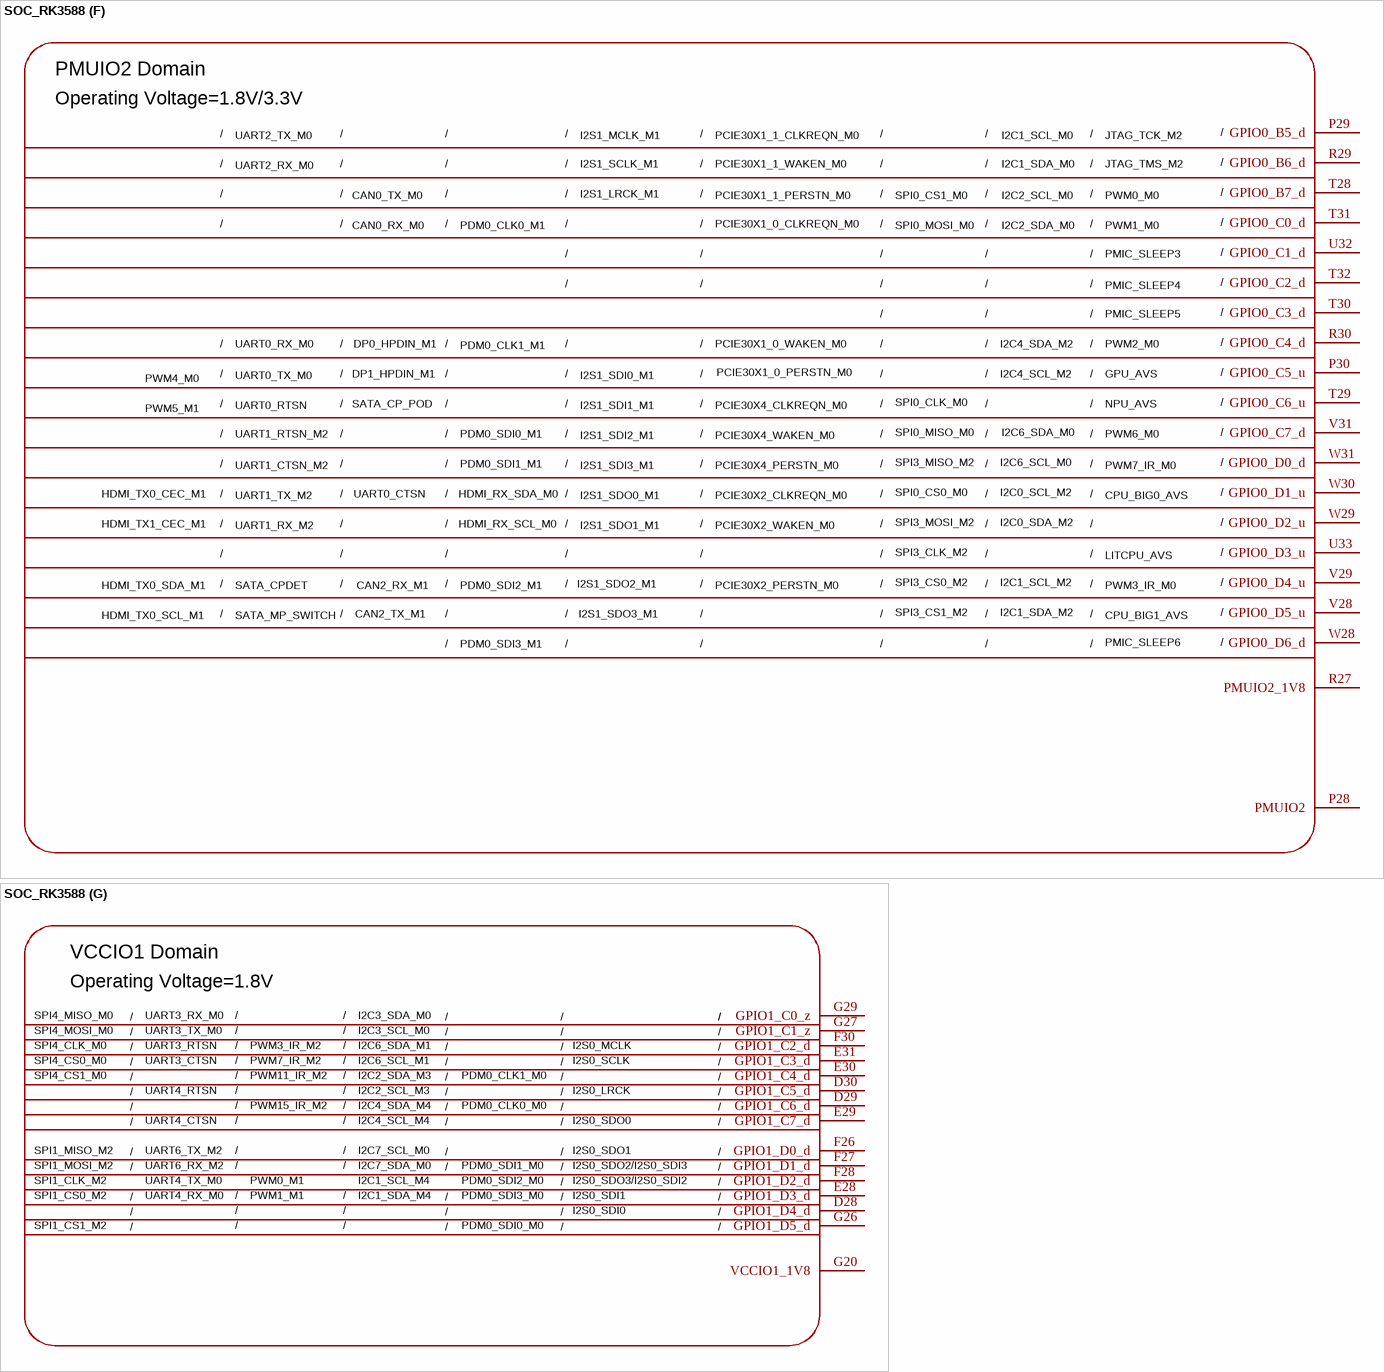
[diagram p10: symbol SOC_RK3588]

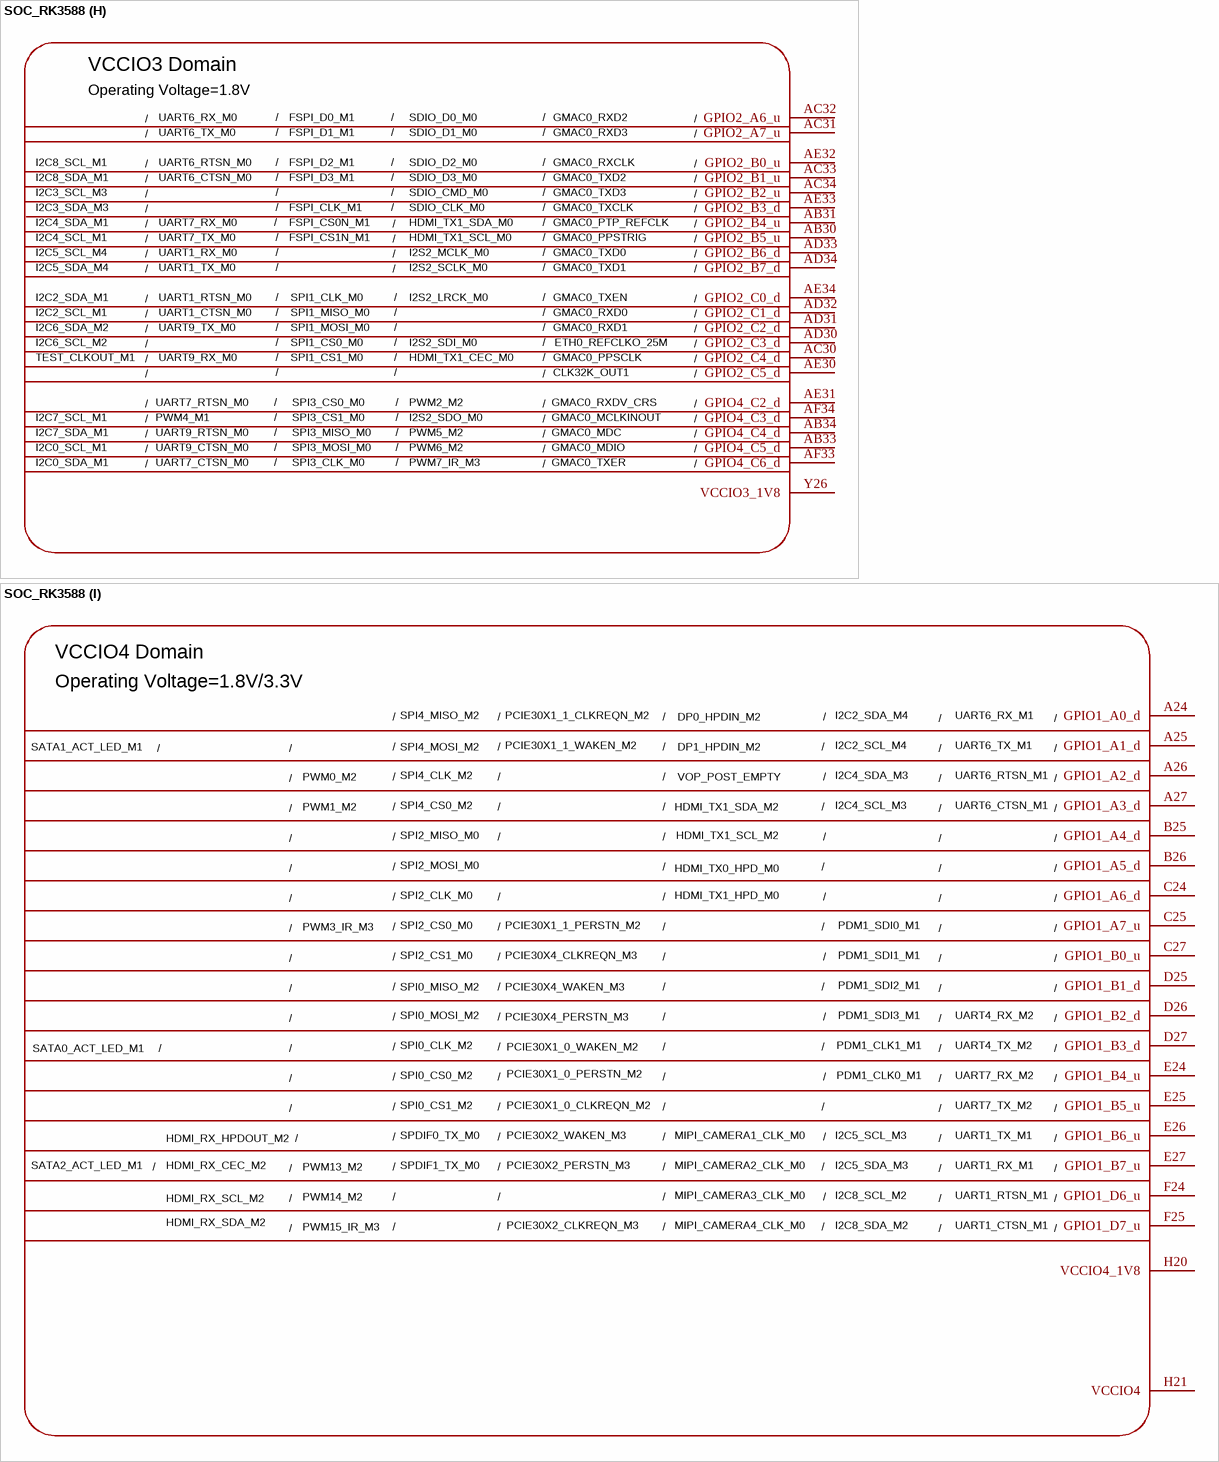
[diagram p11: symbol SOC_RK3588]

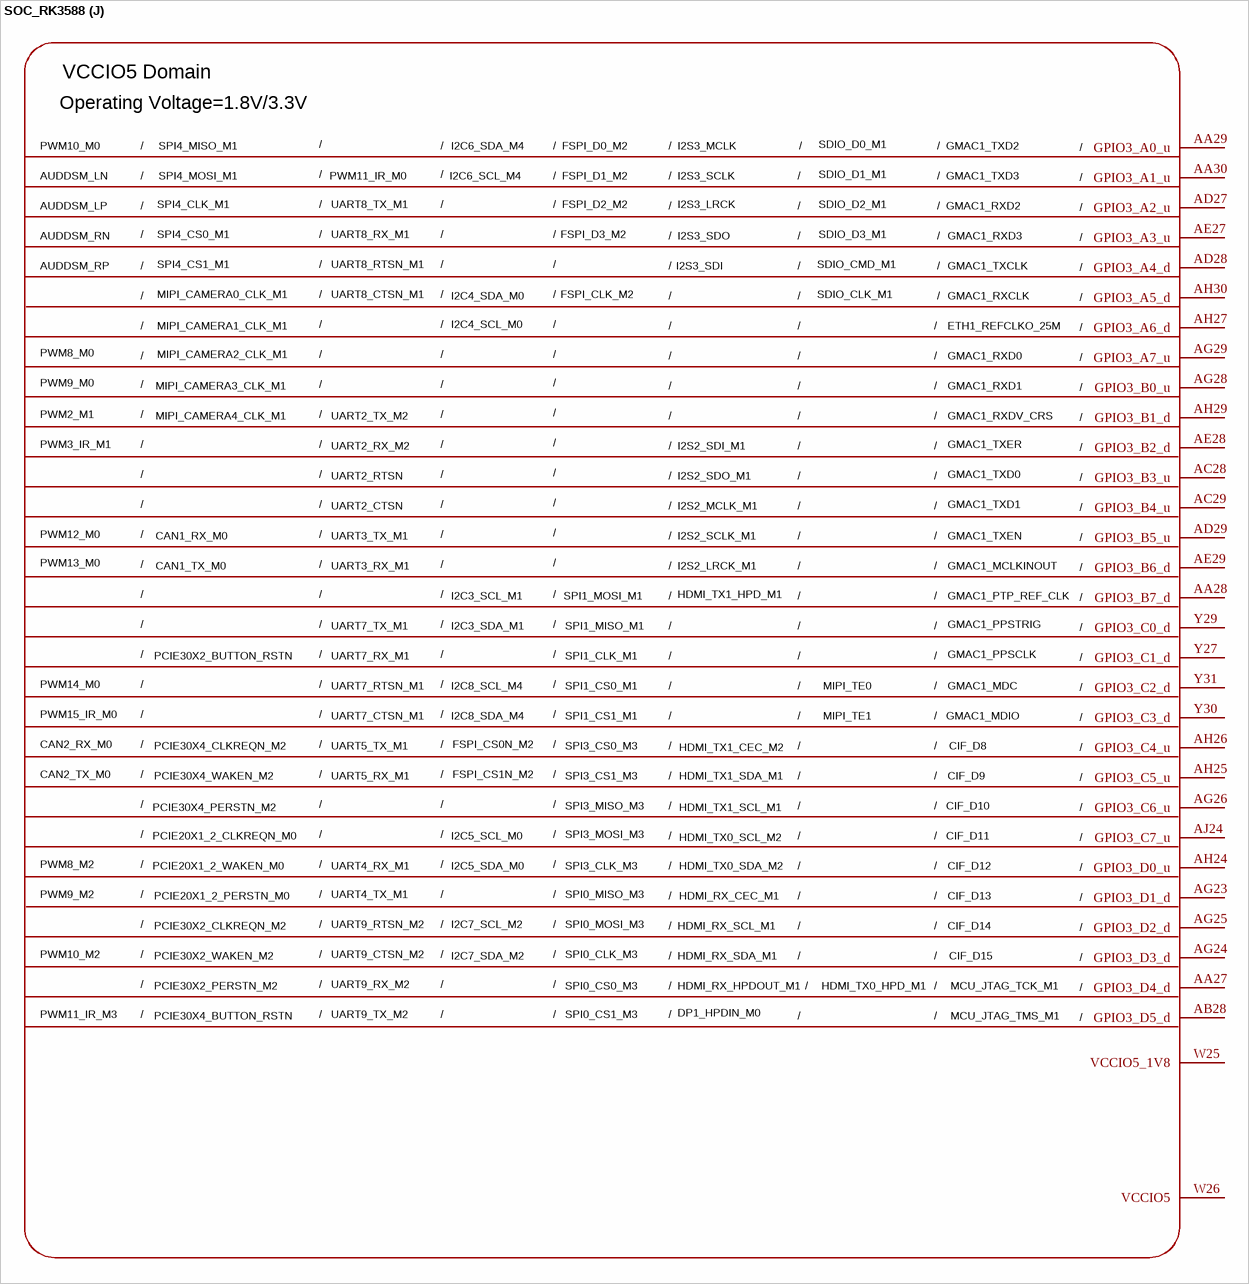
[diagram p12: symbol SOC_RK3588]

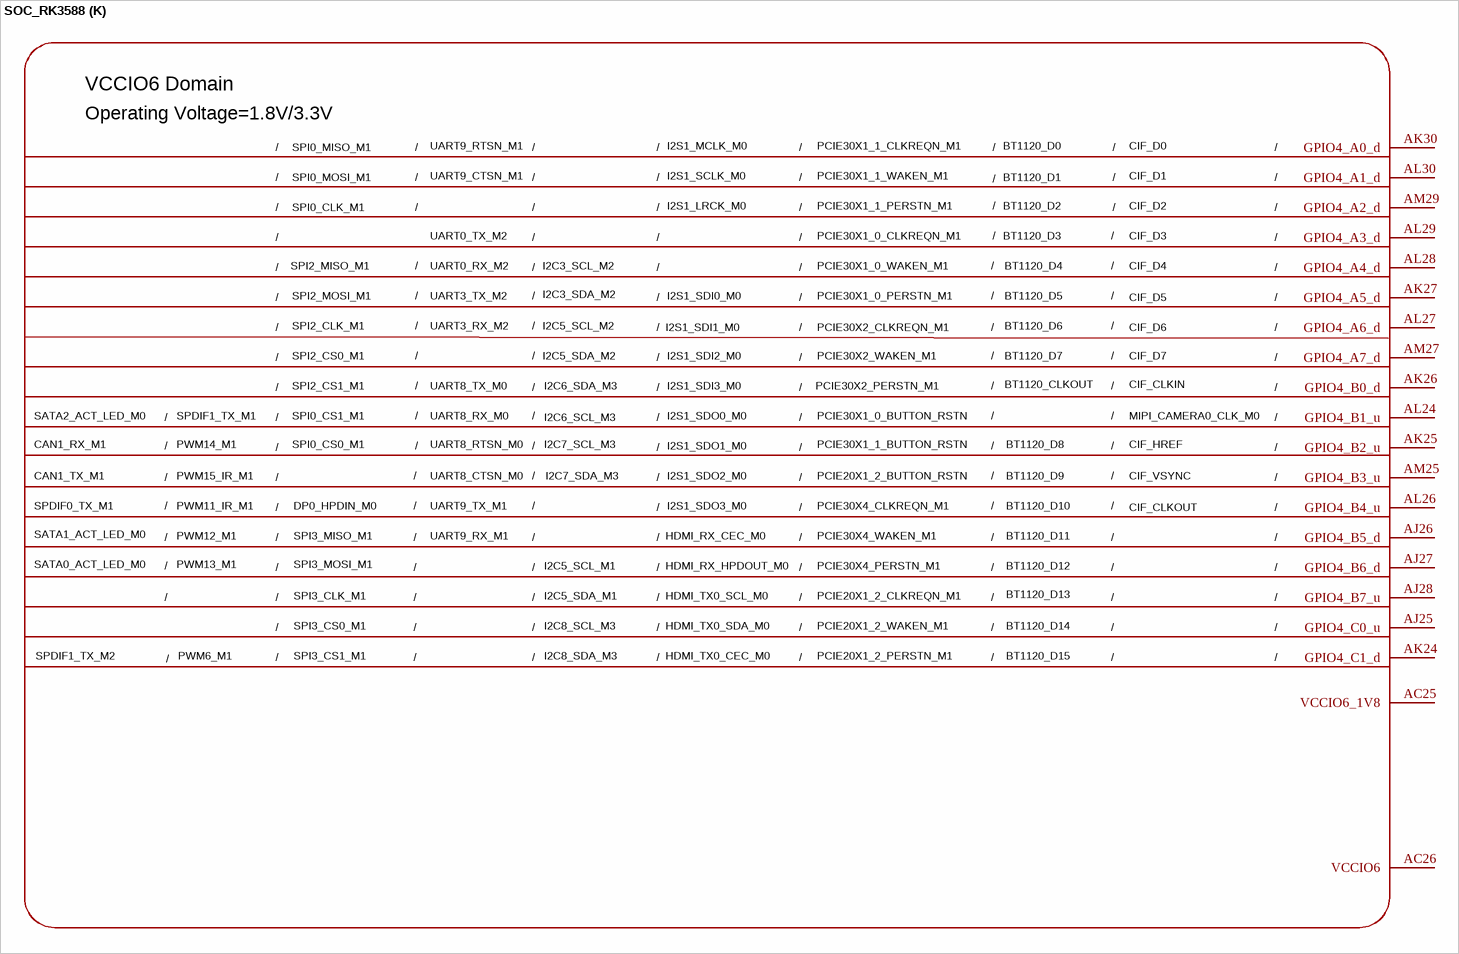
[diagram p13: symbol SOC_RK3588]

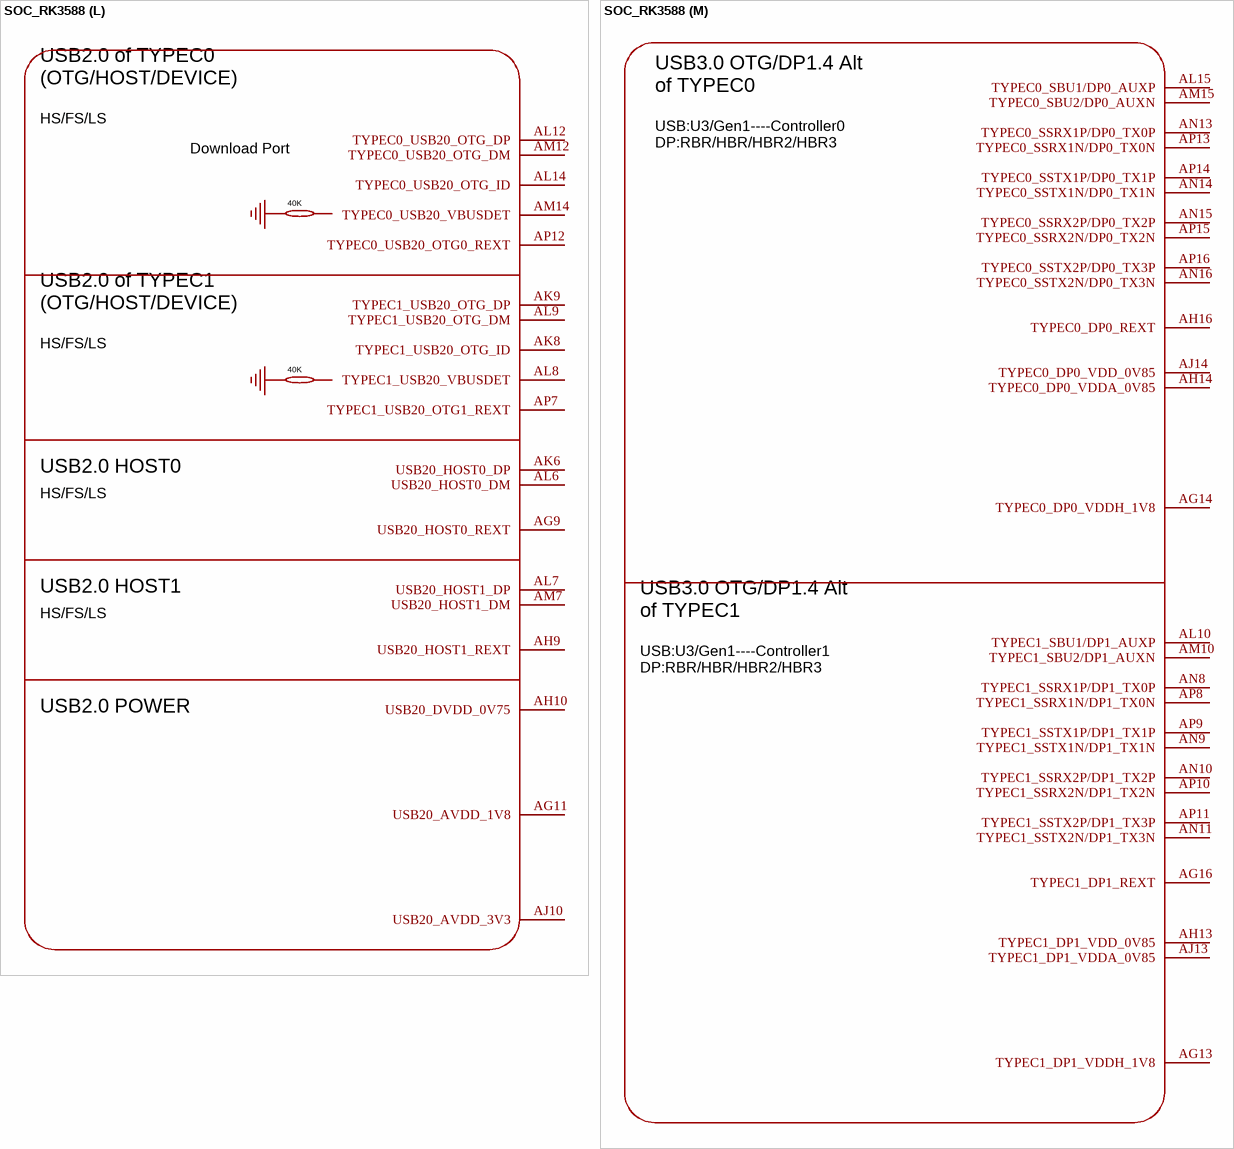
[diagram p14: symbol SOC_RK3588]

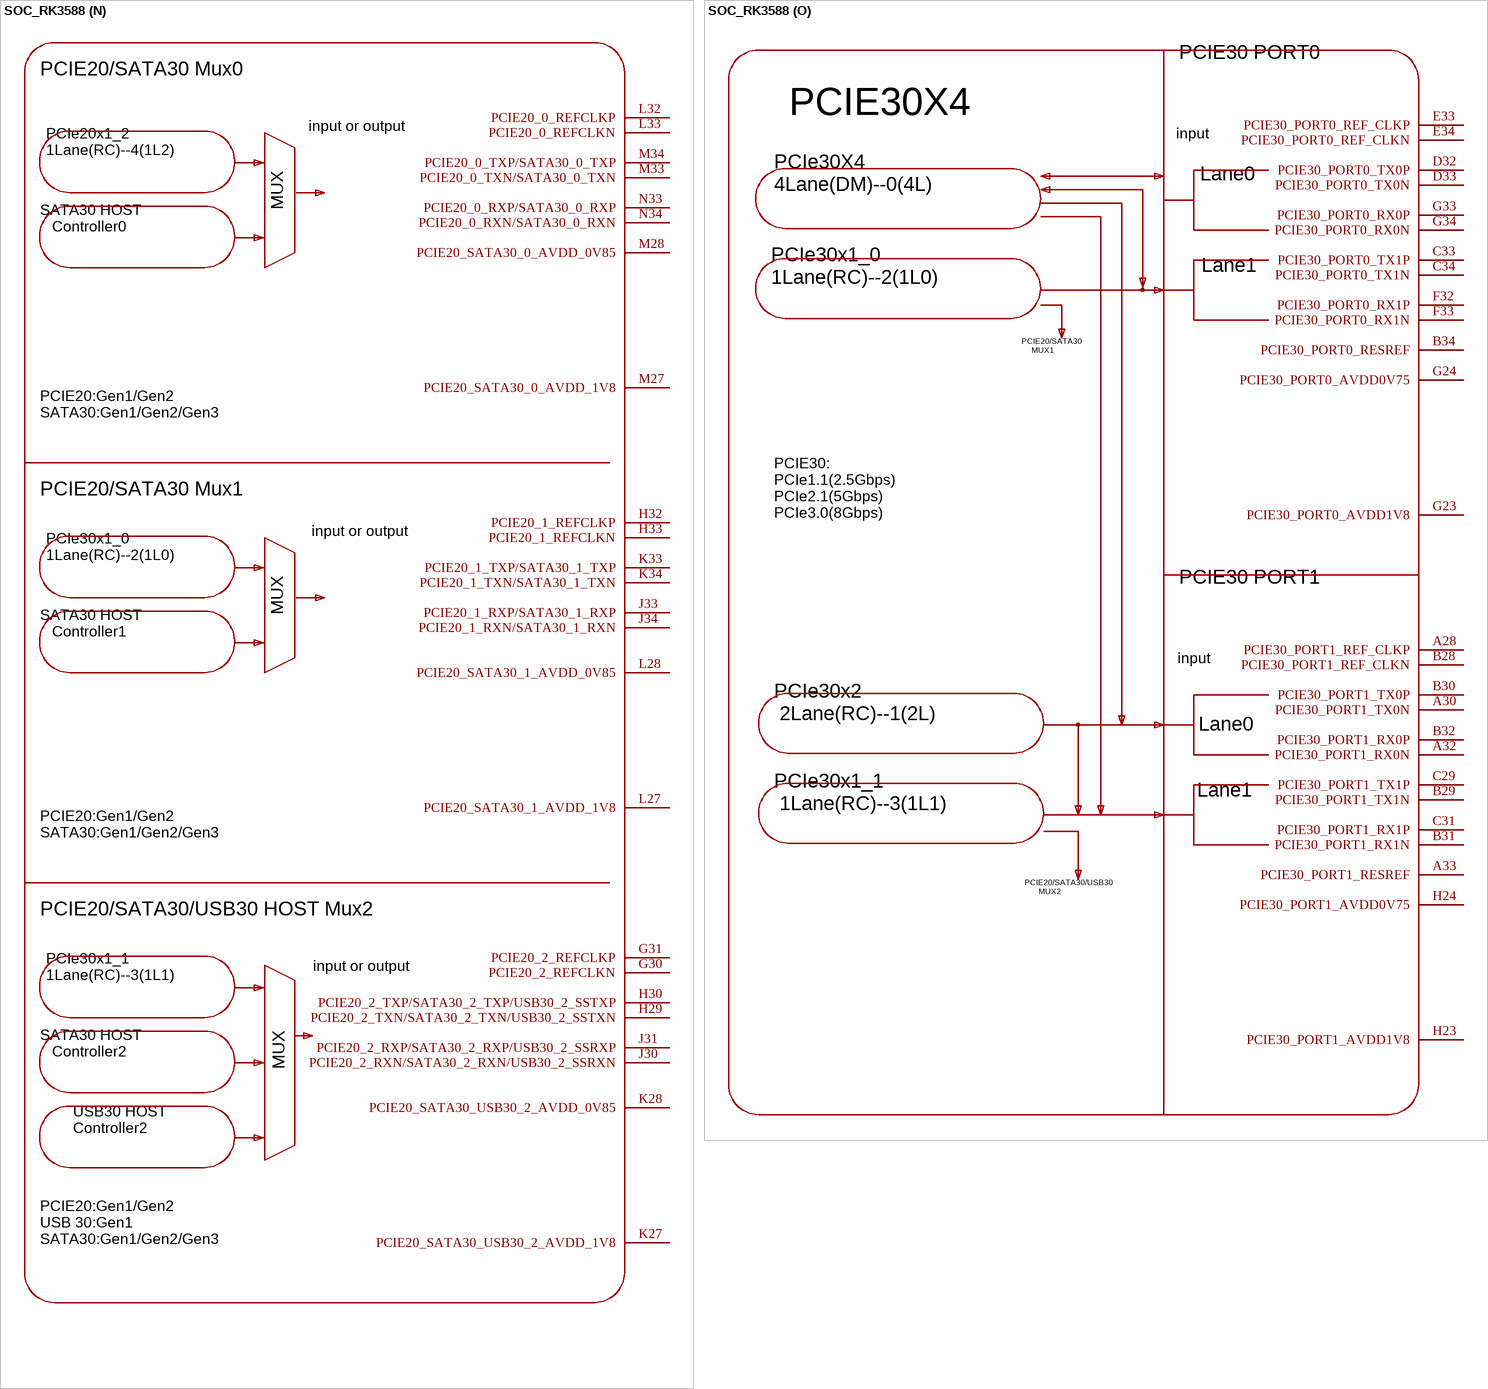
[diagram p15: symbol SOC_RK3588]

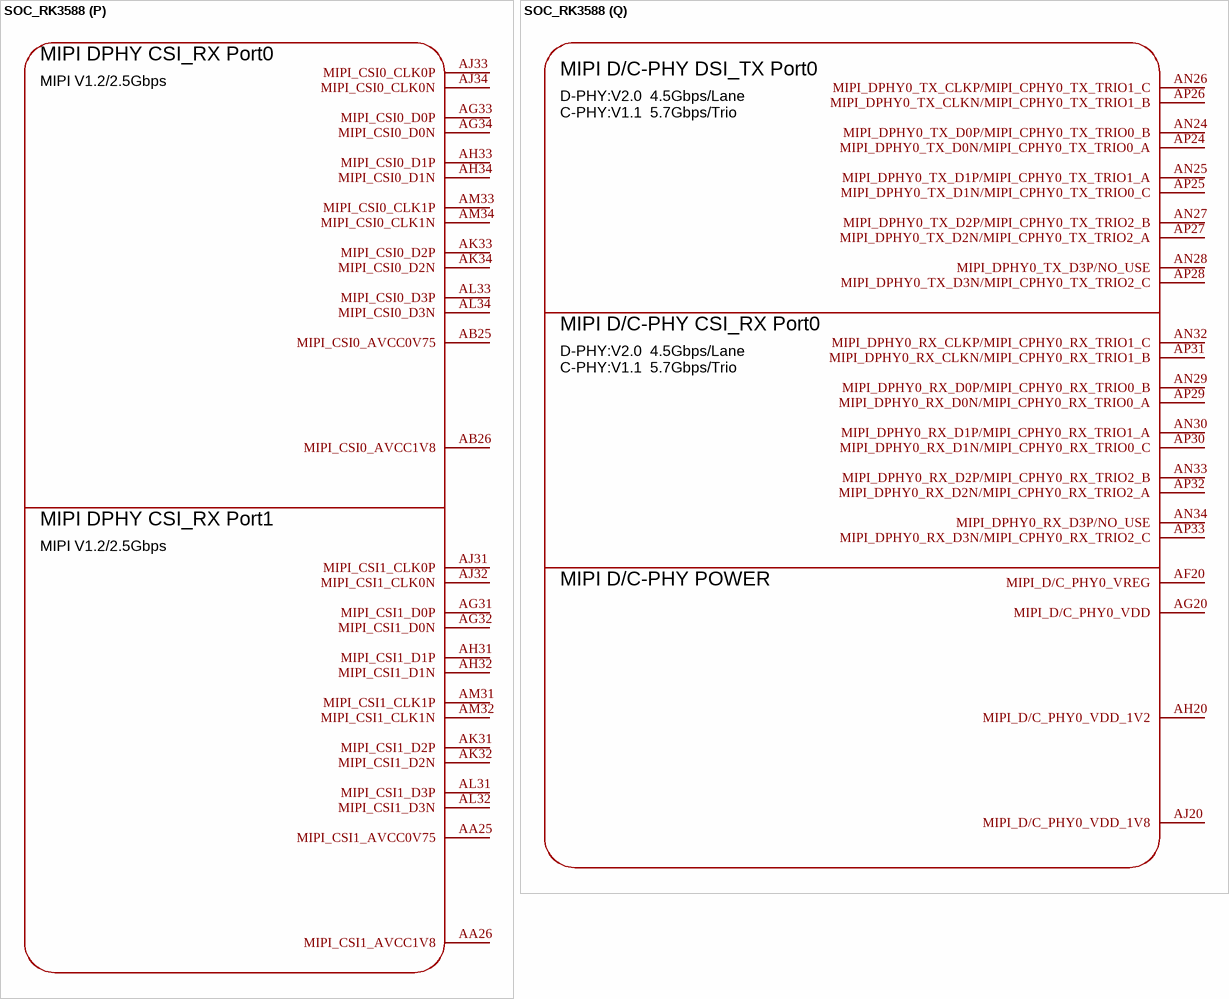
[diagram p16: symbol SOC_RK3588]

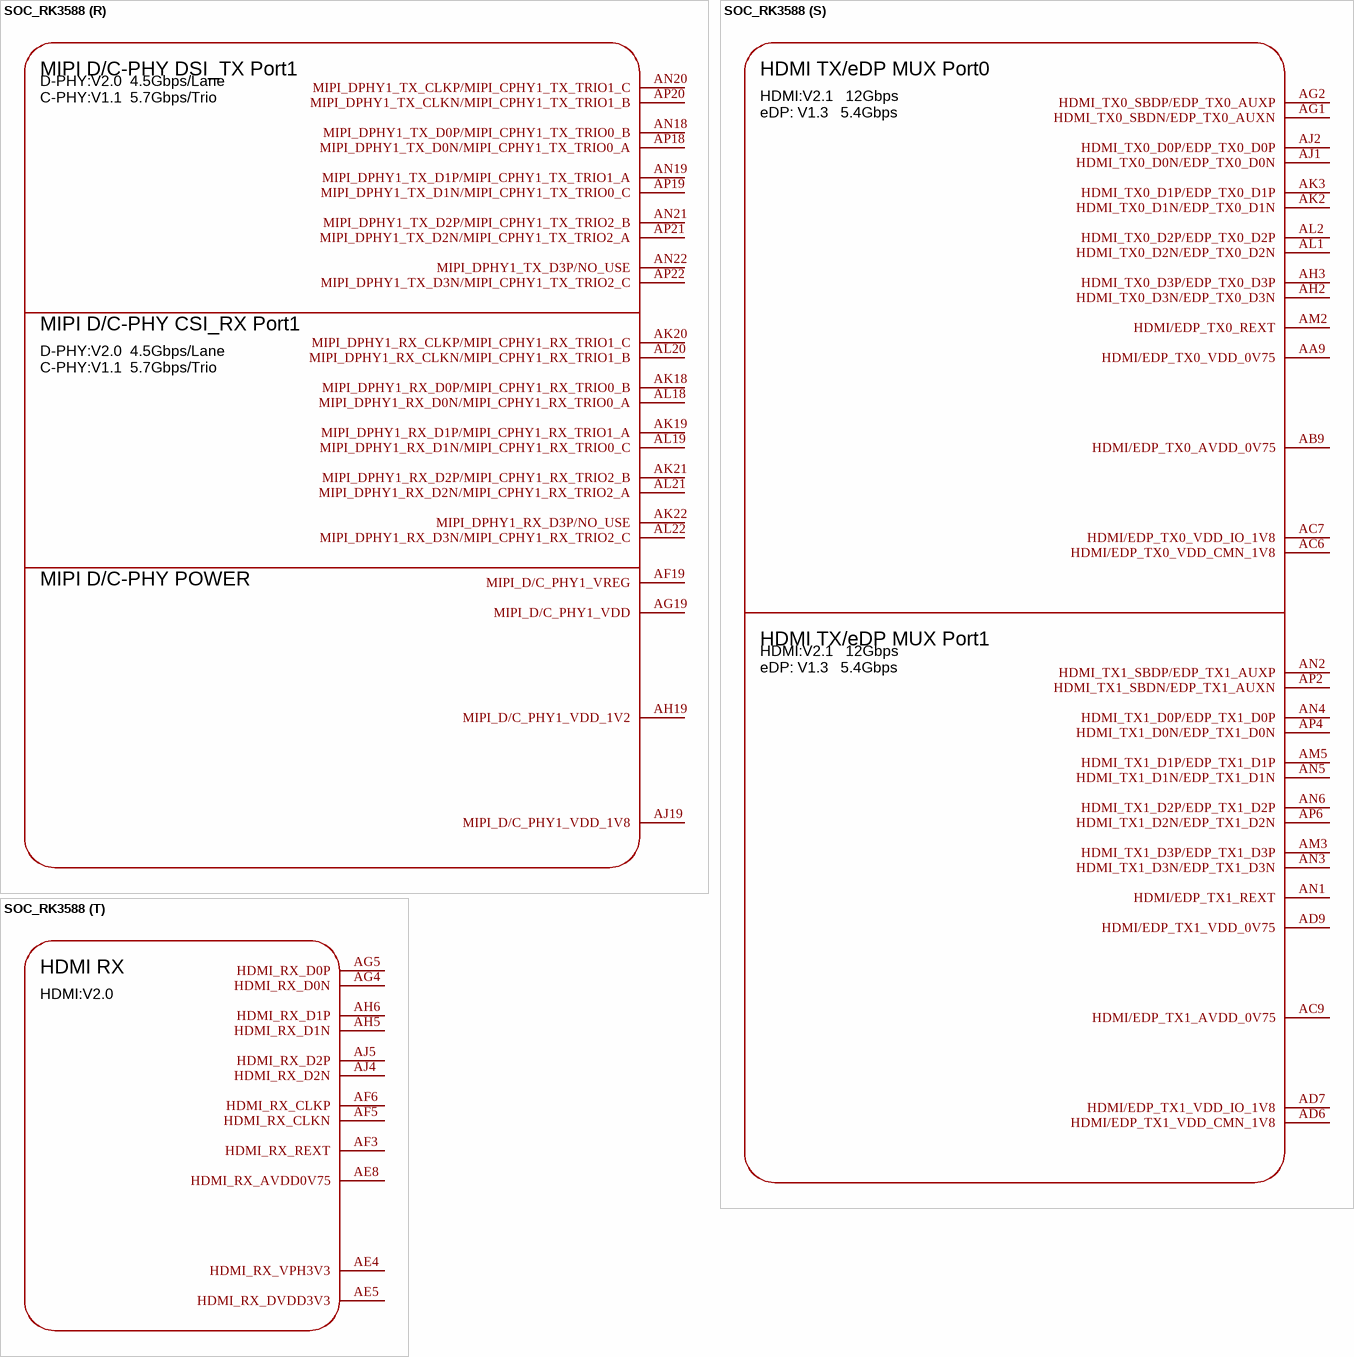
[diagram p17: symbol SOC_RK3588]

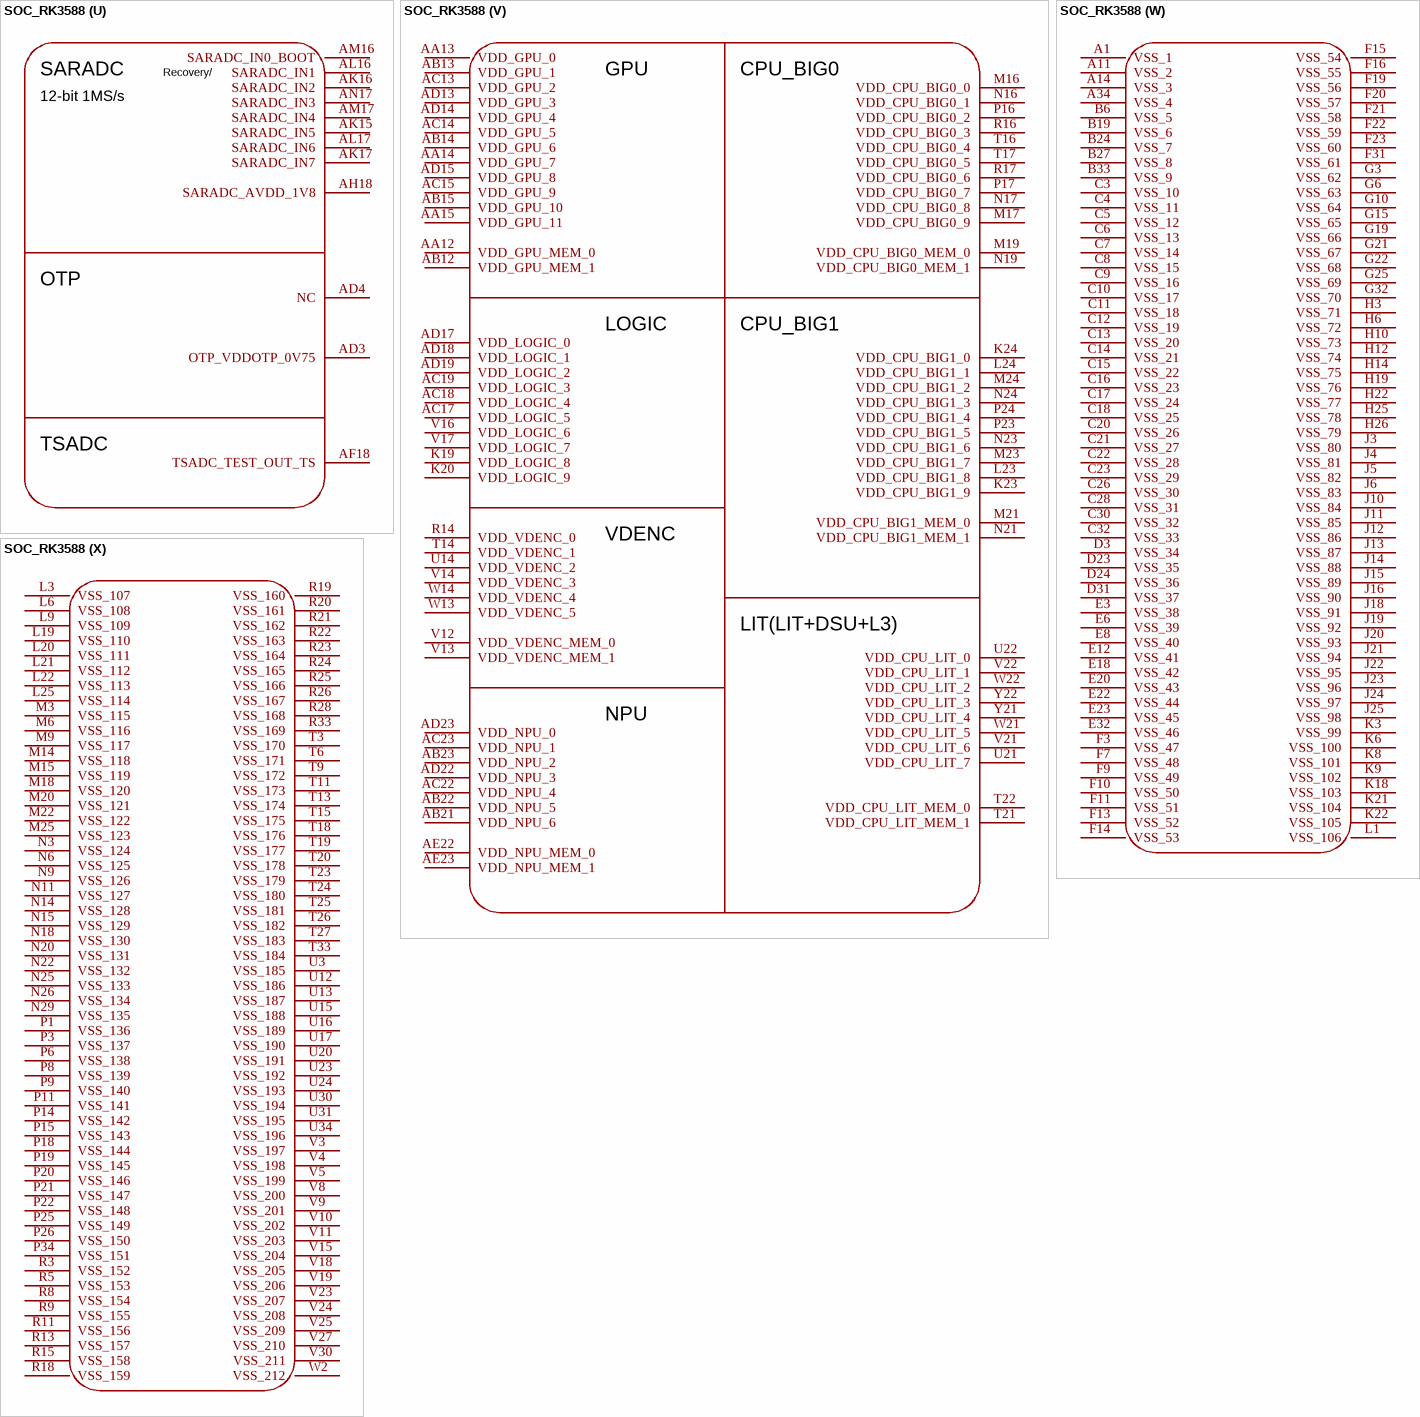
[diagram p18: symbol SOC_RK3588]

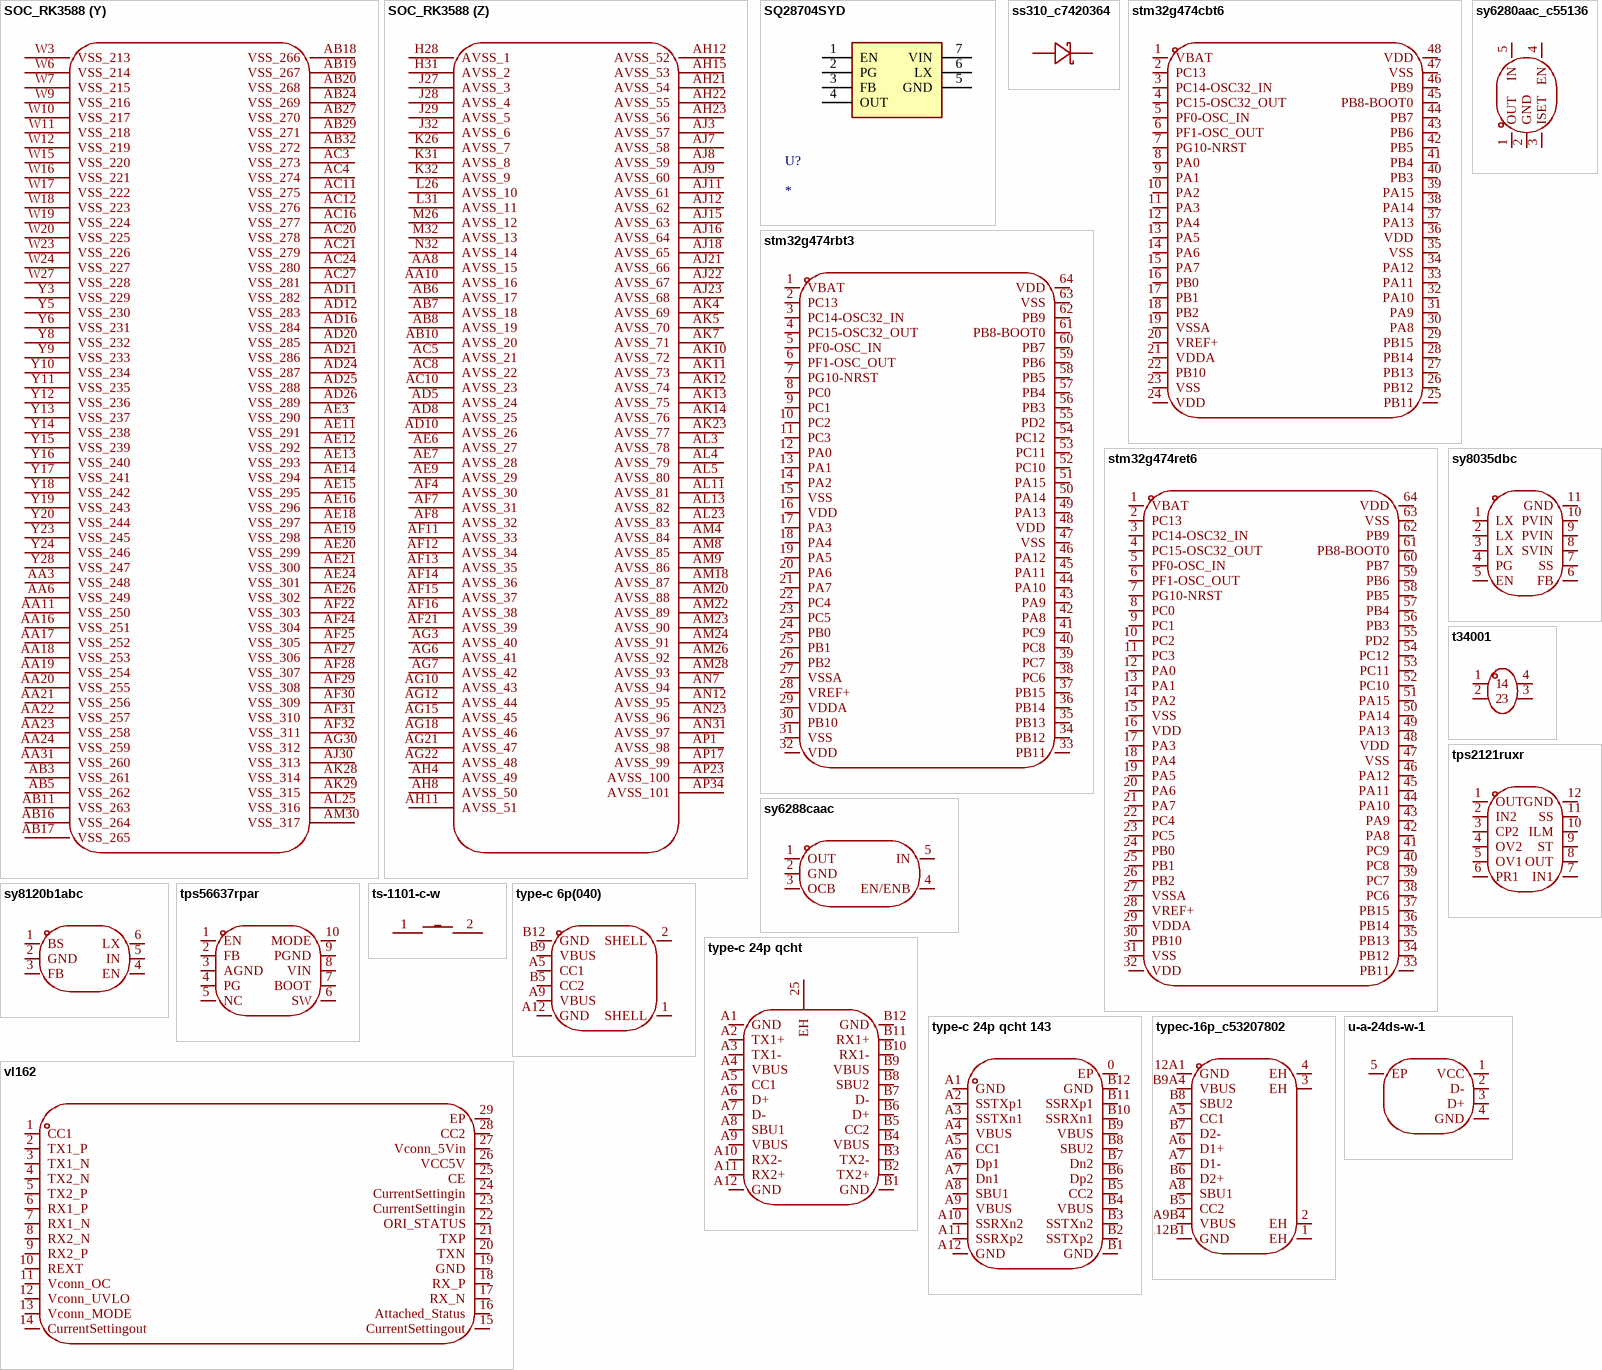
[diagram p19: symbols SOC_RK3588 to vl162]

## SOC_RK3588
designator U??  (value not drawn)
part A pins: AA1 DDR_CH0_DQ14_A, AA2 DDR_CH0_DQ15_A, AA4 DDR_CH0_DQS1N_A, AA5 DDR_CH0_DQS1P_A, AB1 DDR_CH0_DQ9_A, AB2 DDR_CH0_DQ8_A, AB4 DDR_CH0_DM1_A, AC1 DDR_CH0_DQ10_A, AC2 DDR_CH0_DQ11_A, B1 DDR_CH0_DQ11_B, C1 DDR_CH0_DQ9_B, C2 DDR_CH0_DQ10_B, D1 DDR_CH0_DQ15_B, D2 DDR_CH0_DQ8_B, E1 DDR_CH0_DQ13_B, E2 DDR_CH0_DQ14_B, E4 DDR_CH0_DM1_B, F1 DDR_CH0_DQ4_B, F2 DDR_CH0_DQ12_B, F4 DDR_CH0_DQS1N_B, F5 DDR_CH0_DQS1P_B, G1 DDR_CH0_DQ6_B, G2 DDR_CH0_DQ5_B, G4 DDR_CH0_DM0_B, H1 DDR_CH0_DQ0_B, H2 DDR_CH0_DQ7_B, H4 DDR_CH0_WCK1P_B, H5 DDR_CH0_WCK1N_B, H7 DDR_CH0_ZQ_B, J1 DDR_CH0_DQ2_B, J2 DDR_CH0_DQ1_B, J7 DDR_CH0_DQS0N_B, J8 DDR_CH0_DQS0P_B, K1 DDR_CH0_A4_B, K2 DDR_CH0_DQ3_B, K4 DDR_CH0_WCK0N_B, K5 DDR_CH0_WCK0P_B, K7 DDR_CH0_RESET_B, L2 DDR_CH0_A5_B, L4 DDR_CH0_LP4/4X_CKE1/LP5_CS1_B, L5 DDR_CH0_LP4/4X_CKE0/LP5_CS0_B, L7 DDR_CH0_LP4/4X_CS0_B, L8 DDR_CH0_LP4/4X_CS1_B, L10 DDR_CH0_VDDQ_CK, M1 DDR_CH0_CKB_B, M2 DDR_CH0_CK_B, M5 DDR_CH0_A1_B, M7 DDR_CH0_A6_B, M8 DDR_CH0_A0_B, M10 DDR_CH0_VDDQ_0, M11 DDR_CH0_PLL_AVSS, M12 DDR_CH0_PLL_AVDD1V8, N1 DDR_CH0_CKB_A, N2 DDR_CH0_CK_A, N4 DDR_CH0_A3_B, N5 DDR_CH0_A2_B, N7 DDR_CH0_LP4/4X_CKE1/LP5_CS1_A, N8 DDR_CH0_VDDQ_CKE, N10 DDR_CH0_VDDQ_1, N12 DDR_CH0_PLL_DVDD, N13 DDR_CH0_VDD_MIF_0, P2 DDR_CH0_A5_A, P4 DDR_CH0_A2_A, P5 DDR_CH0_A3_A, P7 DDR_CH0_LP4/4X_CKE0/LP5_CS0_A, P10 DDR_CH0_VDDQ_2, P12 DDR_CH0_VDD_3, P13 DDR_CH0_VDD_MIF_1, R1 DDR_CH0_A4_A, R2 DDR_CH0_DQ3_A, R6 DDR_CH0_LP4/4X_CS0_A, R7 DDR_CH0_LP4/4X_CS1_A, R10 DDR_CH0_VDDQ_3, R12 DDR_CH0_VDD_2, T1 DDR_CH0_DQ2_A, T2 DDR_CH0_DQ1_A, T4 DDR_CH0_RESET_A, T5 DDR_CH0_A6_A, T7 DDR_CH0_A0_A, T8 DDR_CH0_A1_A, T10 DDR_CH0_VDDQ_4, T12 DDR_CH0_VDD_1, U1 DDR_CH0_DQ0_A, U2 DDR_CH0_DQ7_A, U4 DDR_CH0_DQS0N_A, U5 DDR_CH0_DQS0P_A, U11 DDR_CH0_VDD_0, V1 DDR_CH0_DQ6_A, V2 DDR_CH0_DQ5_A, V6 DDR_CH0_WCK0N_A, V7 DDR_CH0_WCK0P_A, W1 DDR_CH0_DQ4_A, W4 DDR_CH0_WCK1P_A, W5 DDR_CH0_WCK1N_A, W8 DDR_CH0_ZQ_A, Y1 DDR_CH0_DQ12_A, Y2 DDR_CH0_DQ13_A, Y4 DDR_CH0_DM0_A
part B pins: A2 DDR_CH1_DQ10_C, A3 DDR_CH1_DQ8_C, A4 DDR_CH1_DQ14_C, A5 DDR_CH1_DQ12_C, A6 DDR_CH1_DQ4_C, A7 DDR_CH1_DQ6_C, A8 DDR_CH1_DQ0_C, A9 DDR_CH1_DQ2_C, A10 DDR_CH1_A4_C, A12 DDR_CH1_CKB_C, A13 DDR_CH1_CKB_D, A15 DDR_CH1_A4_D, A16 DDR_CH1_DQ2_D, A17 DDR_CH1_DQ0_D, A18 DDR_CH1_DQ6_D, A19 DDR_CH1_DQ4_D, A20 DDR_CH1_DQ12_D, A21 DDR_CH1_DQ14_D, A22 DDR_CH1_DQ8_D, A23 DDR_CH1_DQ10_D, B2 DDR_CH1_DQ11_C, B3 DDR_CH1_DQ9_C, B4 DDR_CH1_DQ15_C, B5 DDR_CH1_DQ13_C, B7 DDR_CH1_DQ5_C, B8 DDR_CH1_DQ7_C, B9 DDR_CH1_DQ1_C, B10 DDR_CH1_DQ3_C, B11 DDR_CH1_A5_C, B12 DDR_CH1_CK_C, B13 DDR_CH1_CK_D, B14 DDR_CH1_A5_D, B15 DDR_CH1_DQ3_D, B16 DDR_CH1_DQ1_D, B17 DDR_CH1_DQ7_D, B18 DDR_CH1_DQ5_D, B20 DDR_CH1_DQ13_D, B21 DDR_CH1_DQ15_D, B22 DDR_CH1_DQ9_D, B23 DDR_CH1_DQ11_D, C19 DDR_CH1_RESET_D, D4 DDR_CH1_DM1_C, D5 DDR_CH1_DQS1N_C, D7 DDR_CH1_WCK1P_C, D9 DDR_CH1_DQS0N_C, D10 DDR_CH1_A6_C, D11 DDR_CH1_LP4/4X_CKE0/LP5_CS0_C, D13 DDR_CH1_A3_C, D14 DDR_CH1_A6_D, D16 DDR_CH1_LP4/4X_CKE0/LP5_CS0_D, D17 DDR_CH1_WCK0N_D, D19 DDR_CH1_LP4/4X_CS1_D, D20 DDR_CH1_DM0_D, D21 DDR_CH1_DQS1P_D, D22 DDR_CH1_DM1_D, E5 DDR_CH1_DQS1P_C, E7 DDR_CH1_WCK1N_C, E9 DDR_CH1_DQS0P_C, E10 DDR_CH1_RESET_C, E11 DDR_CH1_LP4/4X_CKE1/LP5_CS1_C, E13 DDR_CH1_A2_C, E14 DDR_CH1_A3_D, E16 DDR_CH1_LP4/4X_CKE1/LP5_CS1_D, E17 DDR_CH1_WCK0P_D, E19 DDR_CH1_LP4/4X_CS0_D, E21 DDR_CH1_DQS1N_D, F8 DDR_CH1_DM0_C, F12 DDR_CH1_A1_C, F18 DDR_CH1_ZQ_D, G8 DDR_CH1_ZQ_C, G9 DDR_CH1_WCK0P_C, G11 DDR_CH1_LP4/4X_CS0_C, G12 DDR_CH1_A0_C, G13 DDR_CH1_A2_D, G14 DDR_CH1_A1_D, G16 DDR_CH1_DQS0N_D, G18 DDR_CH1_WCK1N_D, H9 DDR_CH1_WCK0N_C, H11 DDR_CH1_LP4/4X_CS1_C, H13 DDR_CH1_VDDQ_CKE, H15 DDR_CH1_A0_D, H16 DDR_CH1_DQS0P_D, H18 DDR_CH1_WCK1P_D, K11 DDR_CH1_VDDQ_0, K12 DDR_CH1_VDDQ_1, K13 DDR_CH1_VDDQ_2, K14 DDR_CH1_VDDQ_3, K15 DDR_CH1_VDDQ_4, K16 DDR_CH1_PLL_AVDD1V8, L11 DDR_CH1_VDD_0, L12 DDR_CH1_VDD_1, L13 DDR_CH1_VDD_2, L14 DDR_CH1_VDD_3, L15 DDR_CH1_PLL_DVDD, L16 DDR_CH1_PLL_AVSS, L17 DDR_CH1_VDD_MIF_0, L18 DDR_CH1_VDD_MIF_1, M13 DDR_CH1_VDDQ_CK
part C pins: AA32 GPIO2_D5_u, AA33 GPIO2_D3_u, AA34 GPIO2_A3_d, V26 EMMCIO_1V8, V32 GPIO2_D2_u, V33 GPIO2_D7_u, V34 GPIO2_A1_d, W32 GPIO2_D6_u, W33 GPIO2_D1_u, W34 GPIO2_A0_u, Y32 GPIO2_D4_u, Y33 GPIO2_D0_u, Y34 GPIO2_A2_d
part D pins: AA7 VCCIO2_1V8, AD1 GPIO4_D1_u, AD2 GPIO4_D0_u, AE1 GPIO4_D5_d, AE2 GPIO4_D4_u, AF1 GPIO4_D3_u, AF2 GPIO4_D2_u, Y7 VCCIO2
part E pins: K29 GPIO0_B2_u, K30 GPIO0_B1_z, L29 GPIO0_B3_z, L30 GPIO0_B0_z, M29 TVSS, M30 GPIO0_A7_u, M31 NPOR_u, N27 OSC_1V8, N28 PMUIO1_1V8, N30 GPIO0_A6_z, N31 GPIO0_A5_d, P27 PMU_0V75, P31 GPIO0_A4_u, P32 GPIO0_A1_z, P33 GPIO0_A0_d, R31 GPIO0_A3_d, R32 GPIO0_A2_d, R34 XIN_24M, T34 XOUT_24M, U18 PLL_AVDD1V8, U19 PLL_AVSS, V20 PLL_DVDD0V75
part F pins: P28 PMUIO2, P29 GPIO0_B5_d, P30 GPIO0_C5_u, R27 PMUIO2_1V8, R29 GPIO0_B6_d, R30 GPIO0_C4_d, T28 GPIO0_B7_d, T29 GPIO0_C6_u, T30 GPIO0_C3_d, T31 GPIO0_C0_d, T32 GPIO0_C2_d, U32 GPIO0_C1_d, U33 GPIO0_D3_u, V28 GPIO0_D5_u, V29 GPIO0_D4_u, V31 GPIO0_C7_d, W28 GPIO0_D6_d, W29 GPIO0_D2_u, W30 GPIO0_D1_u, W31 GPIO0_D0_d
part G pins: D28 GPIO1_D4_d, D29 GPIO1_C6_d, D30 GPIO1_C5_d, E28 GPIO1_D3_d, E29 GPIO1_C7_d, E30 GPIO1_C4_d, E31 GPIO1_C3_d, F26 GPIO1_D0_d, F27 GPIO1_D1_d, F28 GPIO1_D2_d, F30 GPIO1_C2_d, G20 VCCIO1_1V8, G26 GPIO1_D5_d, G27 GPIO1_C1_z, G29 GPIO1_C0_z
part H pins: AB30 GPIO2_B5_u, AB31 GPIO2_B4_u, AB33 GPIO4_C5_d, AB34 GPIO4_C4_d, AC30 GPIO2_C4_d, AC31 GPIO2_A7_u, AC32 GPIO2_A6_u, AC33 GPIO2_B1_u, AC34 GPIO2_B2_u, AD30 GPIO2_C3_d, AD31 GPIO2_C2_d, AD32 GPIO2_C1_d, AD33 GPIO2_B6_d, AD34 GPIO2_B7_d, AE30 GPIO2_C5_d, AE31 GPIO4_C2_d, AE32 GPIO2_B0_u, AE33 GPIO2_B3_d, AE34 GPIO2_C0_d, AF33 GPIO4_C6_d, AF34 GPIO4_C3_d, Y26 VCCIO3_1V8
part I pins: A24 GPIO1_A0_d, A25 GPIO1_A1_d, A26 GPIO1_A2_d, A27 GPIO1_A3_d, B25 GPIO1_A4_d, B26 GPIO1_A5_d, C24 GPIO1_A6_d, C25 GPIO1_A7_u, C27 GPIO1_B0_u, D25 GPIO1_B1_d, D26 GPIO1_B2_d, D27 GPIO1_B3_d, E24 GPIO1_B4_u, E25 GPIO1_B5_u, E26 GPIO1_B6_u, E27 GPIO1_B7_u, F24 GPIO1_D6_u, F25 GPIO1_D7_u, H20 VCCIO4_1V8, H21 VCCIO4
part J pins: AA27 GPIO3_D4_d, AA28 GPIO3_B7_d, AA29 GPIO3_A0_u, AA30 GPIO3_A1_u, AB28 GPIO3_D5_d, AC28 GPIO3_B3_u, AC29 GPIO3_B4_u, AD27 GPIO3_A2_u, AD28 GPIO3_A4_d, AD29 GPIO3_B5_u, AE27 GPIO3_A3_u, AE28 GPIO3_B2_d, AE29 GPIO3_B6_d, AG23 GPIO3_D1_d, AG24 GPIO3_D3_d, AG25 GPIO3_D2_d, AG26 GPIO3_C6_u, AG28 GPIO3_B0_u, AG29 GPIO3_A7_u, AH24 GPIO3_D0_u, AH25 GPIO3_C5_u, AH26 GPIO3_C4_u, AH27 GPIO3_A6_d, AH29 GPIO3_B1_d, AH30 GPIO3_A5_d, AJ24 GPIO3_C7_u, W25 VCCIO5_1V8, W26 VCCIO5, Y27 GPIO3_C1_d, Y29 GPIO3_C0_d, Y30 GPIO3_C3_d, Y31 GPIO3_C2_d
part K pins: AC25 VCCIO6_1V8, AC26 VCCIO6, AJ25 GPIO4_C0_u, AJ26 GPIO4_B5_d, AJ27 GPIO4_B6_d, AJ28 GPIO4_B7_u, AK24 GPIO4_C1_d, AK25 GPIO4_B2_u, AK26 GPIO4_B0_d, AK27 GPIO4_A5_d, AK30 GPIO4_A0_d, AL24 GPIO4_B1_u, AL26 GPIO4_B4_u, AL27 GPIO4_A6_d, AL28 GPIO4_A4_d, AL29 GPIO4_A3_d, AL30 GPIO4_A1_d, AM25 GPIO4_B3_u, AM27 GPIO4_A7_d, AM29 GPIO4_A2_d
part L pins: AG9 USB20_HOST0_REXT, AG11 USB20_AVDD_1V8, AH9 USB20_HOST1_REXT, AH10 USB20_DVDD_0V75, AJ10 USB20_AVDD_3V3, AK6 USB20_HOST0_DP, AK8 TYPEC1_USB20_OTG_ID, AK9 TYPEC1_USB20_OTG_DP, AL6 USB20_HOST0_DM, AL7 USB20_HOST1_DP, AL8 TYPEC1_USB20_VBUSDET, AL9 TYPEC1_USB20_OTG_DM, AL12 TYPEC0_USB20_OTG_DP, AL14 TYPEC0_USB20_OTG_ID, AM7 USB20_HOST1_DM, AM12 TYPEC0_USB20_OTG_DM, AM14 TYPEC0_USB20_VBUSDET, AP7 TYPEC1_USB20_OTG1_REXT, AP12 TYPEC0_USB20_OTG0_REXT
part M pins: AG13 TYPEC1_DP1_VDDH_1V8, AG14 TYPEC0_DP0_VDDH_1V8, AG16 TYPEC1_DP1_REXT, AH13 TYPEC1_DP1_VDD_0V85, AH14 TYPEC0_DP0_VDDA_0V85, AH16 TYPEC0_DP0_REXT, AJ13 TYPEC1_DP1_VDDA_0V85, AJ14 TYPEC0_DP0_VDD_0V85, AL10 TYPEC1_SBU1/DP1_AUXP, AL15 TYPEC0_SBU1/DP0_AUXP, AM10 TYPEC1_SBU2/DP1_AUXN, AM15 TYPEC0_SBU2/DP0_AUXN, AN8 TYPEC1_SSRX1P/DP1_TX0P, AN9 TYPEC1_SSTX1N/DP1_TX1N, AN10 TYPEC1_SSRX2P/DP1_TX2P, AN11 TYPEC1_SSTX2N/DP1_TX3N, AN13 TYPEC0_SSRX1P/DP0_TX0P, AN14 TYPEC0_SSTX1N/DP0_TX1N, AN15 TYPEC0_SSRX2P/DP0_TX2P, AN16 TYPEC0_SSTX2N/DP0_TX3N, AP8 TYPEC1_SSRX1N/DP1_TX0N, AP9 TYPEC1_SSTX1P/DP1_TX1P, AP10 TYPEC1_SSRX2N/DP1_TX2N, AP11 TYPEC1_SSTX2P/DP1_TX3P, AP13 TYPEC0_SSRX1N/DP0_TX0N, AP14 TYPEC0_SSTX1P/DP0_TX1P, AP15 TYPEC0_SSRX2N/DP0_TX2N, AP16 TYPEC0_SSTX2P/DP0_TX3P
part N pins: G30 PCIE20_2_REFCLKN, G31 PCIE20_2_REFCLKP, H29 PCIE20_2_TXN/SATA30_2_TXN/USB30_2_SSTXN, H30 PCIE20_2_TXP/SATA30_2_TXP/USB30_2_SSTXP, H32 PCIE20_1_REFCLKP, H33 PCIE20_1_REFCLKN, J30 PCIE20_2_RXN/SATA30_2_RXN/USB30_2_SSRXN, J31 PCIE20_2_RXP/SATA30_2_RXP/USB30_2_SSRXP, J33 PCIE20_1_RXP/SATA30_1_RXP, J34 PCIE20_1_RXN/SATA30_1_RXN, K27 PCIE20_SATA30_USB30_2_AVDD_1V8, K28 PCIE20_SATA30_USB30_2_AVDD_0V85, K33 PCIE20_1_TXP/SATA30_1_TXP, K34 PCIE20_1_TXN/SATA30_1_TXN, L27 PCIE20_SATA30_1_AVDD_1V8, L28 PCIE20_SATA30_1_AVDD_0V85, L32 PCIE20_0_REFCLKP, L33 PCIE20_0_REFCLKN, M27 PCIE20_SATA30_0_AVDD_1V8, M28 PCIE20_SATA30_0_AVDD_0V85, M33 PCIE20_0_TXN/SATA30_0_TXN, M34 PCIE20_0_TXP/SATA30_0_TXP, N33 PCIE20_0_RXP/SATA30_0_RXP, N34 PCIE20_0_RXN/SATA30_0_RXN
part O pins: A28 PCIE30_PORT1_REF_CLKP, A30 PCIE30_PORT1_TX0N, A32 PCIE30_PORT1_RX0N, A33 PCIE30_PORT1_RESREF, B28 PCIE30_PORT1_REF_CLKN, B29 PCIE30_PORT1_TX1N, B30 PCIE30_PORT1_TX0P, B31 PCIE30_PORT1_RX1N, B32 PCIE30_PORT1_RX0P, B34 PCIE30_PORT0_RESREF, C29 PCIE30_PORT1_TX1P, C31 PCIE30_PORT1_RX1P, C33 PCIE30_PORT0_TX1P, C34 PCIE30_PORT0_TX1N, D32 PCIE30_PORT0_TX0P, D33 PCIE30_PORT0_TX0N, E33 PCIE30_PORT0_REF_CLKP, E34 PCIE30_PORT0_REF_CLKN, F32 PCIE30_PORT0_RX1P, F33 PCIE30_PORT0_RX1N, G23 PCIE30_PORT0_AVDD1V8, G24 PCIE30_PORT0_AVDD0V75, G33 PCIE30_PORT0_RX0P, G34 PCIE30_PORT0_RX0N, H23 PCIE30_PORT1_AVDD1V8, H24 PCIE30_PORT1_AVDD0V75
part P pins: AA25 MIPI_CSI1_AVCC0V75, AA26 MIPI_CSI1_AVCC1V8, AB25 MIPI_CSI0_AVCC0V75, AB26 MIPI_CSI0_AVCC1V8, AG31 MIPI_CSI1_D0P, AG32 MIPI_CSI1_D0N, AG33 MIPI_CSI0_D0P, AG34 MIPI_CSI0_D0N, AH31 MIPI_CSI1_D1P, AH32 MIPI_CSI1_D1N, AH33 MIPI_CSI0_D1P, AH34 MIPI_CSI0_D1N, AJ31 MIPI_CSI1_CLK0P, AJ32 MIPI_CSI1_CLK0N, AJ33 MIPI_CSI0_CLK0P, AJ34 MIPI_CSI0_CLK0N, AK31 MIPI_CSI1_D2P, AK32 MIPI_CSI1_D2N, AK33 MIPI_CSI0_D2P, AK34 MIPI_CSI0_D2N, AL31 MIPI_CSI1_D3P, AL32 MIPI_CSI1_D3N, AL33 MIPI_CSI0_D3P, AL34 MIPI_CSI0_D3N, AM31 MIPI_CSI1_CLK1P, AM32 MIPI_CSI1_CLK1N, AM33 MIPI_CSI0_CLK1P, AM34 MIPI_CSI0_CLK1N
part Q pins: AF20 MIPI_D/C_PHY0_VREG, AG20 MIPI_D/C_PHY0_VDD, AH20 MIPI_D/C_PHY0_VDD_1V2, AJ20 MIPI_D/C_PHY0_VDD_1V8, AN24 MIPI_DPHY0_TX_D0P/MIPI_CPHY0_TX_TRIO0_B, AN25 MIPI_DPHY0_TX_D1P/MIPI_CPHY0_TX_TRIO1_A, AN26 MIPI_DPHY0_TX_CLKP/MIPI_CPHY0_TX_TRIO1_C, AN27 MIPI_DPHY0_TX_D2P/MIPI_CPHY0_TX_TRIO2_B, AN28 MIPI_DPHY0_TX_D3P/NO_USE, AN29 MIPI_DPHY0_RX_D0P/MIPI_CPHY0_RX_TRIO0_B, AN30 MIPI_DPHY0_RX_D1P/MIPI_CPHY0_RX_TRIO1_A, AN32 MIPI_DPHY0_RX_CLKP/MIPI_CPHY0_RX_TRIO1_C, AN33 MIPI_DPHY0_RX_D2P/MIPI_CPHY0_RX_TRIO2_B, AN34 MIPI_DPHY0_RX_D3P/NO_USE, AP24 MIPI_DPHY0_TX_D0N/MIPI_CPHY0_TX_TRIO0_A, AP25 MIPI_DPHY0_TX_D1N/MIPI_CPHY0_TX_TRIO0_C, AP26 MIPI_DPHY0_TX_CLKN/MIPI_CPHY0_TX_TRIO1_B, AP27 MIPI_DPHY0_TX_D2N/MIPI_CPHY0_TX_TRIO2_A, AP28 MIPI_DPHY0_TX_D3N/MIPI_CPHY0_TX_TRIO2_C, AP29 MIPI_DPHY0_RX_D0N/MIPI_CPHY0_RX_TRIO0_A, AP30 MIPI_DPHY0_RX_D1N/MIPI_CPHY0_RX_TRIO0_C, AP31 MIPI_DPHY0_RX_CLKN/MIPI_CPHY0_RX_TRIO1_B, AP32 MIPI_DPHY0_RX_D2N/MIPI_CPHY0_RX_TRIO2_A, AP33 MIPI_DPHY0_RX_D3N/MIPI_CPHY0_RX_TRIO2_C
part R pins: AF19 MIPI_D/C_PHY1_VREG, AG19 MIPI_D/C_PHY1_VDD, AH19 MIPI_D/C_PHY1_VDD_1V2, AJ19 MIPI_D/C_PHY1_VDD_1V8, AK18 MIPI_DPHY1_RX_D0P/MIPI_CPHY1_RX_TRIO0_B, AK19 MIPI_DPHY1_RX_D1P/MIPI_CPHY1_RX_TRIO1_A, AK20 MIPI_DPHY1_RX_CLKP/MIPI_CPHY1_RX_TRIO1_C, AK21 MIPI_DPHY1_RX_D2P/MIPI_CPHY1_RX_TRIO2_B, AK22 MIPI_DPHY1_RX_D3P/NO_USE, AL18 MIPI_DPHY1_RX_D0N/MIPI_CPHY1_RX_TRIO0_A, AL19 MIPI_DPHY1_RX_D1N/MIPI_CPHY1_RX_TRIO0_C, AL20 MIPI_DPHY1_RX_CLKN/MIPI_CPHY1_RX_TRIO1_B, AL21 MIPI_DPHY1_RX_D2N/MIPI_CPHY1_RX_TRIO2_A, AL22 MIPI_DPHY1_RX_D3N/MIPI_CPHY1_RX_TRIO2_C, AN18 MIPI_DPHY1_TX_D0P/MIPI_CPHY1_TX_TRIO0_B, AN19 MIPI_DPHY1_TX_D1P/MIPI_CPHY1_TX_TRIO1_A, AN20 MIPI_DPHY1_TX_CLKP/MIPI_CPHY1_TX_TRIO1_C, AN21 MIPI_DPHY1_TX_D2P/MIPI_CPHY1_TX_TRIO2_B, AN22 MIPI_DPHY1_TX_D3P/NO_USE, AP18 MIPI_DPHY1_TX_D0N/MIPI_CPHY1_TX_TRIO0_A, AP19 MIPI_DPHY1_TX_D1N/MIPI_CPHY1_TX_TRIO0_C, AP20 MIPI_DPHY1_TX_CLKN/MIPI_CPHY1_TX_TRIO1_B, AP21 MIPI_DPHY1_TX_D2N/MIPI_CPHY1_TX_TRIO2_A, AP22 MIPI_DPHY1_TX_D3N/MIPI_CPHY1_TX_TRIO2_C
part S pins: AA9 HDMI/EDP_TX0_VDD_0V75, AB9 HDMI/EDP_TX0_AVDD_0V75, AC6 HDMI/EDP_TX0_VDD_CMN_1V8, AC7 HDMI/EDP_TX0_VDD_IO_1V8, AC9 HDMI/EDP_TX1_AVDD_0V75, AD6 HDMI/EDP_TX1_VDD_CMN_1V8, AD7 HDMI/EDP_TX1_VDD_IO_1V8, AD9 HDMI/EDP_TX1_VDD_0V75, AG1 HDMI_TX0_SBDN/EDP_TX0_AUXN, AG2 HDMI_TX0_SBDP/EDP_TX0_AUXP, AH2 HDMI_TX0_D3N/EDP_TX0_D3N, AH3 HDMI_TX0_D3P/EDP_TX0_D3P, AJ1 HDMI_TX0_D0N/EDP_TX0_D0N, AJ2 HDMI_TX0_D0P/EDP_TX0_D0P, AK2 HDMI_TX0_D1N/EDP_TX0_D1N, AK3 HDMI_TX0_D1P/EDP_TX0_D1P, AL1 HDMI_TX0_D2N/EDP_TX0_D2N, AL2 HDMI_TX0_D2P/EDP_TX0_D2P, AM2 HDMI/EDP_TX0_REXT, AM3 HDMI_TX1_D3P/EDP_TX1_D3P, AM5 HDMI_TX1_D1P/EDP_TX1_D1P, AN1 HDMI/EDP_TX1_REXT, AN2 HDMI_TX1_SBDP/EDP_TX1_AUXP, AN3 HDMI_TX1_D3N/EDP_TX1_D3N, AN4 HDMI_TX1_D0P/EDP_TX1_D0P, AN5 HDMI_TX1_D1N/EDP_TX1_D1N, AN6 HDMI_TX1_D2P/EDP_TX1_D2P, AP2 HDMI_TX1_SBDN/EDP_TX1_AUXN, AP4 HDMI_TX1_D0N/EDP_TX1_D0N, AP6 HDMI_TX1_D2N/EDP_TX1_D2N
part T pins: AE4 HDMI_RX_VPH3V3, AE5 HDMI_RX_DVDD3V3, AE8 HDMI_RX_AVDD0V75, AF3 HDMI_RX_REXT, AF5 HDMI_RX_CLKN, AF6 HDMI_RX_CLKP, AG4 HDMI_RX_D0N, AG5 HDMI_RX_D0P, AH5 HDMI_RX_D1N, AH6 HDMI_RX_D1P, AJ4 HDMI_RX_D2N, AJ5 HDMI_RX_D2P
part U pins: AD3 OTP_VDDOTP_0V75, AD4 NC, AF18 TSADC_TEST_OUT_TS, AH18 SARADC_AVDD_1V8, AK15 SARADC_IN5, AK16 SARADC_IN2, AK17 SARADC_IN7, AL16 SARADC_IN1, AL17 SARADC_IN6, AM16 SARADC_IN0_BOOT, AM17 SARADC_IN4, AN17 SARADC_IN3
part V pins: AA12 VDD_GPU_MEM_0, AA13 VDD_GPU_0, AA14 VDD_GPU_7, AA15 VDD_GPU_11, AB12 VDD_GPU_MEM_1, AB13 VDD_GPU_1, AB14 VDD_GPU_6, AB15 VDD_GPU_10, AB21 VDD_NPU_6, AB22 VDD_NPU_5, AB23 VDD_NPU_2, AC13 VDD_GPU_2, AC14 VDD_GPU_5, AC15 VDD_GPU_9, AC17 VDD_LOGIC_5, AC18 VDD_LOGIC_4, AC19 VDD_LOGIC_3, AC22 VDD_NPU_4, AC23 VDD_NPU_1, AD13 VDD_GPU_3, AD14 VDD_GPU_4, AD15 VDD_GPU_8, AD17 VDD_LOGIC_0, AD18 VDD_LOGIC_1, AD19 VDD_LOGIC_2, AD22 VDD_NPU_3, AD23 VDD_NPU_0, AE22 VDD_NPU_MEM_0, AE23 VDD_NPU_MEM_1, K19 VDD_LOGIC_8, K20 VDD_LOGIC_9, K23 VDD_CPU_BIG1_9, K24 VDD_CPU_BIG1_0, L23 VDD_CPU_BIG1_8, L24 VDD_CPU_BIG1_1, M16 VDD_CPU_BIG0_0, M17 VDD_CPU_BIG0_9, M19 VDD_CPU_BIG0_MEM_0, M21 VDD_CPU_BIG1_MEM_0, M23 VDD_CPU_BIG1_7, M24 VDD_CPU_BIG1_2, N16 VDD_CPU_BIG0_1, N17 VDD_CPU_BIG0_8, N19 VDD_CPU_BIG0_MEM_1, N21 VDD_CPU_BIG1_MEM_1, N23 VDD_CPU_BIG1_6, N24 VDD_CPU_BIG1_3, P16 VDD_CPU_BIG0_2, P17 VDD_CPU_BIG0_7, P23 VDD_CPU_BIG1_5, P24 VDD_CPU_BIG1_4, R14 VDD_VDENC_0, R16 VDD_CPU_BIG0_3, R17 VDD_CPU_BIG0_6, T14 VDD_VDENC_1, T16 VDD_CPU_BIG0_4, T17 VDD_CPU_BIG0_5, T21 VDD_CPU_LIT_MEM_1, T22 VDD_CPU_LIT_MEM_0, U14 VDD_VDENC_2, U21 VDD_CPU_LIT_7, U22 VDD_CPU_LIT_0, V12 VDD_VDENC_MEM_0, V13 VDD_VDENC_MEM_1, V14 VDD_VDENC_3, V16 VDD_LOGIC_6, V17 VDD_LOGIC_7, V21 VDD_CPU_LIT_6, V22 VDD_CPU_LIT_1, W13 VDD_VDENC_5, W14 VDD_VDENC_4, W21 VDD_CPU_LIT_5, W22 VDD_CPU_LIT_2, Y21 VDD_CPU_LIT_4, Y22 VDD_CPU_LIT_3
part W pins: A1 VSS_1, A11 VSS_2, A14 VSS_3, A34 VSS_4, B6 VSS_5, B19 VSS_6, B24 VSS_7, B27 VSS_8, B33 VSS_9, C3 VSS_10, C4 VSS_11, C5 VSS_12, C6 VSS_13, C7 VSS_14, C8 VSS_15, C9 VSS_16, C10 VSS_17, C11 VSS_18, C12 VSS_19, C13 VSS_20, C14 VSS_21, C15 VSS_22, C16 VSS_23, C17 VSS_24, C18 VSS_25, C20 VSS_26, C21 VSS_27, C22 VSS_28, C23 VSS_29, C26 VSS_30, C28 VSS_31, C30 VSS_32, C32 VSS_33, D3 VSS_34, D23 VSS_35, D24 VSS_36, D31 VSS_37, E3 VSS_38, E6 VSS_39, E8 VSS_40, E12 VSS_41, E18 VSS_42, E20 VSS_43, E22 VSS_44, E23 VSS_45, E32 VSS_46, F3 VSS_47, F7 VSS_48, F9 VSS_49, F10 VSS_50, F11 VSS_51, F13 VSS_52, F14 VSS_53, F15 VSS_54, F16 VSS_55, F19 VSS_56, F20 VSS_57, F21 VSS_58, F22 VSS_59, F23 VSS_60, F31 VSS_61, G3 VSS_62, G6 VSS_63, G10 VSS_64, G15 VSS_65, G19 VSS_66, G21 VSS_67, G22 VSS_68, G25 VSS_69, G32 VSS_70, H3 VSS_71, H6 VSS_72, H10 VSS_73, H12 VSS_74, H14 VSS_75, H19 VSS_76, H22 VSS_77, H25 VSS_78, H26 VSS_79, J3 VSS_80, J4 VSS_81, J5 VSS_82, J6 VSS_83, J10 VSS_84, J11 VSS_85, J12 VSS_86, J13 VSS_87, J14 VSS_88, J15 VSS_89, J16 VSS_90, J18 VSS_91, J19 VSS_92, J20 VSS_93, J21 VSS_94, J22 VSS_95, J23 VSS_96, J24 VSS_97, J25 VSS_98, K3 VSS_99, K6 VSS_100, K8 VSS_101, K9 VSS_102, K18 VSS_103, K21 VSS_104, K22 VSS_105, L1 VSS_106
part X pins: L3 VSS_107, L6 VSS_108, L9 VSS_109, L19 VSS_110, L20 VSS_111, L21 VSS_112, L22 VSS_113, L25 VSS_114, M3 VSS_115, M6 VSS_116, M9 VSS_117, M14 VSS_118, M15 VSS_119, M18 VSS_120, M20 VSS_121, M22 VSS_122, M25 VSS_123, N3 VSS_124, N6 VSS_125, N9 VSS_126, N11 VSS_127, N14 VSS_128, N15 VSS_129, N18 VSS_130, N20 VSS_131, N22 VSS_132, N25 VSS_133, N26 VSS_134, N29 VSS_135, P1 VSS_136, P3 VSS_137, P6 VSS_138, P8 VSS_139, P9 VSS_140, P11 VSS_141, P14 VSS_142, P15 VSS_143, P18 VSS_144, P19 VSS_145, P20 VSS_146, P21 VSS_147, P22 VSS_148, P25 VSS_149, P26 VSS_150, P34 VSS_151, R3 VSS_152, R5 VSS_153, R8 VSS_154, R9 VSS_155, R11 VSS_156, R13 VSS_157, R15 VSS_158, R18 VSS_159, R19 VSS_160, R20 VSS_161, R21 VSS_162, R22 VSS_163, R23 VSS_164, R24 VSS_165, R25 VSS_166, R26 VSS_167, R28 VSS_168, R33 VSS_169, T3 VSS_170, T6 VSS_171, T9 VSS_172, T11 VSS_173, T13 VSS_174, T15 VSS_175, T18 VSS_176, T19 VSS_177, T20 VSS_178, T23 VSS_179, T24 VSS_180, T25 VSS_181, T26 VSS_182, T27 VSS_183, T33 VSS_184, U3 VSS_185, U12 VSS_186, U13 VSS_187, U15 VSS_188, U16 VSS_189, U17 VSS_190, U20 VSS_191, U23 VSS_192, U24 VSS_193, U30 VSS_194, U31 VSS_195, U34 VSS_196, V3 VSS_197, V4 VSS_198, V5 VSS_199, V8 VSS_200, V9 VSS_201, V10 VSS_202, V11 VSS_203, V15 VSS_204, V18 VSS_205, V19 VSS_206, V23 VSS_207, V24 VSS_208, V25 VSS_209, V27 VSS_210, V30 VSS_211, W2 VSS_212
part Y pins: AA3 VSS_248, AA6 VSS_249, AA11 VSS_250, AA16 VSS_251, AA17 VSS_252, AA18 VSS_253, AA19 VSS_254, AA20 VSS_255, AA21 VSS_256, AA22 VSS_257, AA23 VSS_258, AA24 VSS_259, AA31 VSS_260, AB3 VSS_261, AB5 VSS_262, AB11 VSS_263, AB16 VSS_264, AB17 VSS_265, AB18 VSS_266, AB19 VSS_267, AB20 VSS_268, AB24 VSS_269, AB27 VSS_270, AB29 VSS_271, AB32 VSS_272, AC3 VSS_273, AC4 VSS_274, AC11 VSS_275, AC12 VSS_276, AC16 VSS_277, AC20 VSS_278, AC21 VSS_279, AC24 VSS_280, AC27 VSS_281, AD11 VSS_282, AD12 VSS_283, AD16 VSS_284, AD20 VSS_285, AD21 VSS_286, AD24 VSS_287, AD25 VSS_288, AD26 VSS_289, AE3 VSS_290, AE11 VSS_291, AE12 VSS_292, AE13 VSS_293, AE14 VSS_294, AE15 VSS_295, AE16 VSS_296, AE18 VSS_297, AE19 VSS_298, AE20 VSS_299, AE21 VSS_300, AE24 VSS_301, AE26 VSS_302, AF22 VSS_303, AF24 VSS_304, AF25 VSS_305, AF27 VSS_306, AF28 VSS_307, AF29 VSS_308, AF30 VSS_309, AF31 VSS_310, AF32 VSS_311, AG30 VSS_312, AJ30 VSS_313, AK28 VSS_314, AK29 VSS_315, AL25 VSS_316, AM30 VSS_317, W3 VSS_213, W6 VSS_214, W7 VSS_215, W9 VSS_216, W10 VSS_217, W11 VSS_218, W12 VSS_219, W15 VSS_220, W16 VSS_221, W17 VSS_222, W18 VSS_223, W19 VSS_224, W20 VSS_225, W23 VSS_226, W24 VSS_227, W27 VSS_228, Y3 VSS_229, Y5 VSS_230, Y6 VSS_231, Y8 VSS_232, Y9 VSS_233, Y10 VSS_234, Y11 VSS_235, Y12 VSS_236, Y13 VSS_237, Y14 VSS_238, Y15 VSS_239, Y16 VSS_240, Y17 VSS_241, Y18 VSS_242, Y19 VSS_243, Y20 VSS_244, Y23 VSS_245, Y24 VSS_246, Y28 VSS_247
part Z pins: AA8 AVSS_15, AA10 AVSS_16, AB6 AVSS_17, AB7 AVSS_18, AB8 AVSS_19, AB10 AVSS_20, AC5 AVSS_21, AC8 AVSS_22, AC10 AVSS_23, AD5 AVSS_24, AD8 AVSS_25, AD10 AVSS_26, AE6 AVSS_27, AE7 AVSS_28, AE9 AVSS_29, AF4 AVSS_30, AF7 AVSS_31, AF8 AVSS_32, AF11 AVSS_33, AF12 AVSS_34, AF13 AVSS_35, AF14 AVSS_36, AF15 AVSS_37, AF16 AVSS_38, AF21 AVSS_39, AG3 AVSS_40, AG6 AVSS_41, AG7 AVSS_42, AG10 AVSS_43, AG12 AVSS_44, AG15 AVSS_45, AG18 AVSS_46, AG21 AVSS_47, AG22 AVSS_48, AH4 AVSS_49, AH8 AVSS_50, AH11 AVSS_51, AH12 AVSS_52, AH15 AVSS_53, AH21 AVSS_54, AH22 AVSS_55, AH23 AVSS_56, AJ3 AVSS_57, AJ7 AVSS_58, AJ8 AVSS_59, AJ9 AVSS_60, AJ11 AVSS_61, AJ12 AVSS_62, AJ15 AVSS_63, AJ16 AVSS_64, AJ18 AVSS_65, AJ21 AVSS_66, AJ22 AVSS_67, AJ23 AVSS_68, AK4 AVSS_69, AK5 AVSS_70, AK7 AVSS_71, AK10 AVSS_72, AK11 AVSS_73, AK12 AVSS_74, AK13 AVSS_75, AK14 AVSS_76, AK23 AVSS_77, AL3 AVSS_78, AL4 AVSS_79, AL5 AVSS_80, AL11 AVSS_81, AL13 AVSS_82, AL23 AVSS_83, AM4 AVSS_84, AM8 AVSS_85, AM9 AVSS_86, AM18 AVSS_87, AM20 AVSS_88, AM22 AVSS_89, AM23 AVSS_90, AM24 AVSS_91, AM26 AVSS_92, AM28 AVSS_93, AN7 AVSS_94, AN12 AVSS_95, AN23 AVSS_96, AN31 AVSS_97, AP1 AVSS_98, AP17 AVSS_99, AP23 AVSS_100, AP34 AVSS_101, H28 AVSS_1, H31 AVSS_2, J27 AVSS_3, J28 AVSS_4, J29 AVSS_5, J32 AVSS_6, K26 AVSS_7, K31 AVSS_8, K32 AVSS_9, L26 AVSS_10, L31 AVSS_11, M26 AVSS_12, M32 AVSS_13, N32 AVSS_14

## SQ28704SYD
designator U?
4A synchronous step-down regulator, DFN2x2-7
footprint SQ28704SYD_DFN2X2-7 (DFN 2x2-7)
pins: 1 EN, 2 PG, 3 FB, 4 OUT, 5 GND, 6 LX, 7 VIN

## ss310_c7420364
designator D??  (value not drawn)
二极管配置:独立式;正向压降(Vf):850mV@3A;直流反向耐压(Vr):100V;整流电流:3A;; Manufacturer: R+O(宏嘉诚); ManufacturerPart: SS310; AddInBom: yes; ModelId: 7e24bebe6cd74171ae8c9de6fc5b78aa; ModelName: SMA_L4.3-W2.6-LS5.0-FD; ModelTransform: 198.4248,103.5431,0,180,0,0,-0.001,0,0; Diode Configuration: 独立式; Voltage - DC Reverse(Vr): 100V; Current - Rectified: 3A; Reverse Leakage Current (Ir): 50uA@100V; Operating Junction Temperature Range: -55℃~+150℃; Non-Repetitive Peak Forward Surge Current: 80A
footprint SMA_L4.3-W2.6-LS5.0-FD
pins: 1 A, 2 K

## stm32g474cbt6
designator U??  (value not drawn)
CPU内核:ARM Cortex-M4F;CPU最大主频:170MHz;CPU位数:32 Bit;; Manufacturer: ST(意法半导体); AddInBom: yes; ModelId: 093be70396ff421eb2cdb946d5311efc; ModelName: LQFP-48_L7.0-W7.0-H1.4-LS9.0-P0.50; ModelTransform: 354.331,354.331,0,0,0,0,0,0,0; CPU Maximum Speed: 170MHz; Core Size: 32 Bit; Program Storage Size: 128KB; Program Memory Type: FLASH; Number of I/O: 38; ADC (Bit): 12bit; Oscillator Type: 内置; Voltage - Supply: 1.71V~3.6V
footprint LQFP-48_L7.0-W7.0-P0.50-LS9.0-BL
pins: 1 VBAT, 2 PC13, 3 PC14-OSC32_IN, 4 PC15-OSC32_OUT, 5 PF0-OSC_IN, 6 PF1-OSC_OUT, 7 PG10-NRST, 8 PA0, 9 PA1, 10 PA2, 11 PA3, 12 PA4, 13 PA5, 14 PA6, 15 PA7, 16 PB0, 17 PB1, 18 PB2, 19 VSSA, 20 VREF+, 21 VDDA, 22 PB10, 23 VSS, 24 VDD, 25 PB11, 26 PB12, 27 PB13, 28 PB14, 29 PB15, 30 PA8, 31 PA9, 32 PA10, 33 PA11, 34 PA12, 35 VSS, 36 VDD, 37 PA13, 38 PA14, 39 PA15, 40 PB3, 41 PB4, 42 PB5, 43 PB6, 44 PB7, 45 PB8-BOOT0, 46 PB9, 47 VSS, 48 VDD

## stm32g474rbt3
designator U??  (value not drawn)
CPU内核:ARM Cortex-M4F;CPU最大主频:170MHz;CPU位数:32 Bit;; Manufacturer: ST(意法半导体); AddInBom: yes; ModelId: cd9de06618c44fcf82654c43a457f83c; ModelName: LQFP-64_L10.0-W10.0-H1.4-LS12.0-P0.50; ModelTransform: 472.441,472.441,0,0,0,0,0,0.465,0; CPU Maximum Speed: 170MHz; Core Size: 32 Bit; Program Storage Size: 128KB; Program Memory Type: FLASH; Number of I/O: 52; ADC (Bit): 12bit; Oscillator Type: 内置; Voltage - Supply: 1.71V~3.6V
footprint LQFP-64_L10.0-W10.0-P0.50-LS12.0-BL
pins: 1 VBAT, 2 PC13, 3 PC14-OSC32_IN, 4 PC15-OSC32_OUT, 5 PF0-OSC_IN, 6 PF1-OSC_OUT, 7 PG10-NRST, 8 PC0, 9 PC1, 10 PC2, 11 PC3, 12 PA0, 13 PA1, 14 PA2, 15 VSS, 16 VDD, 17 PA3, 18 PA4, 19 PA5, 20 PA6, 21 PA7, 22 PC4, 23 PC5, 24 PB0, 25 PB1, 26 PB2, 27 VSSA, 28 VREF+, 29 VDDA, 30 PB10, 31 VSS, 32 VDD, 33 PB11, 34 PB12, 35 PB13, 36 PB14, 37 PB15, 38 PC6, 39 PC7, 40 PC8, 41 PC9, 42 PA8, 43 PA9, 44 PA10, 45 PA11, 46 PA12, 47 VSS, 48 VDD, 49 PA13, 50 PA14, 51 PA15, 52 PC10, 53 PC11, 54 PC12, 55 PD2, 56 PB3, 57 PB4, 58 PB5, 59 PB6, 60 PB7, 61 PB8-BOOT0, 62 PB9, 63 VSS, 64 VDD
